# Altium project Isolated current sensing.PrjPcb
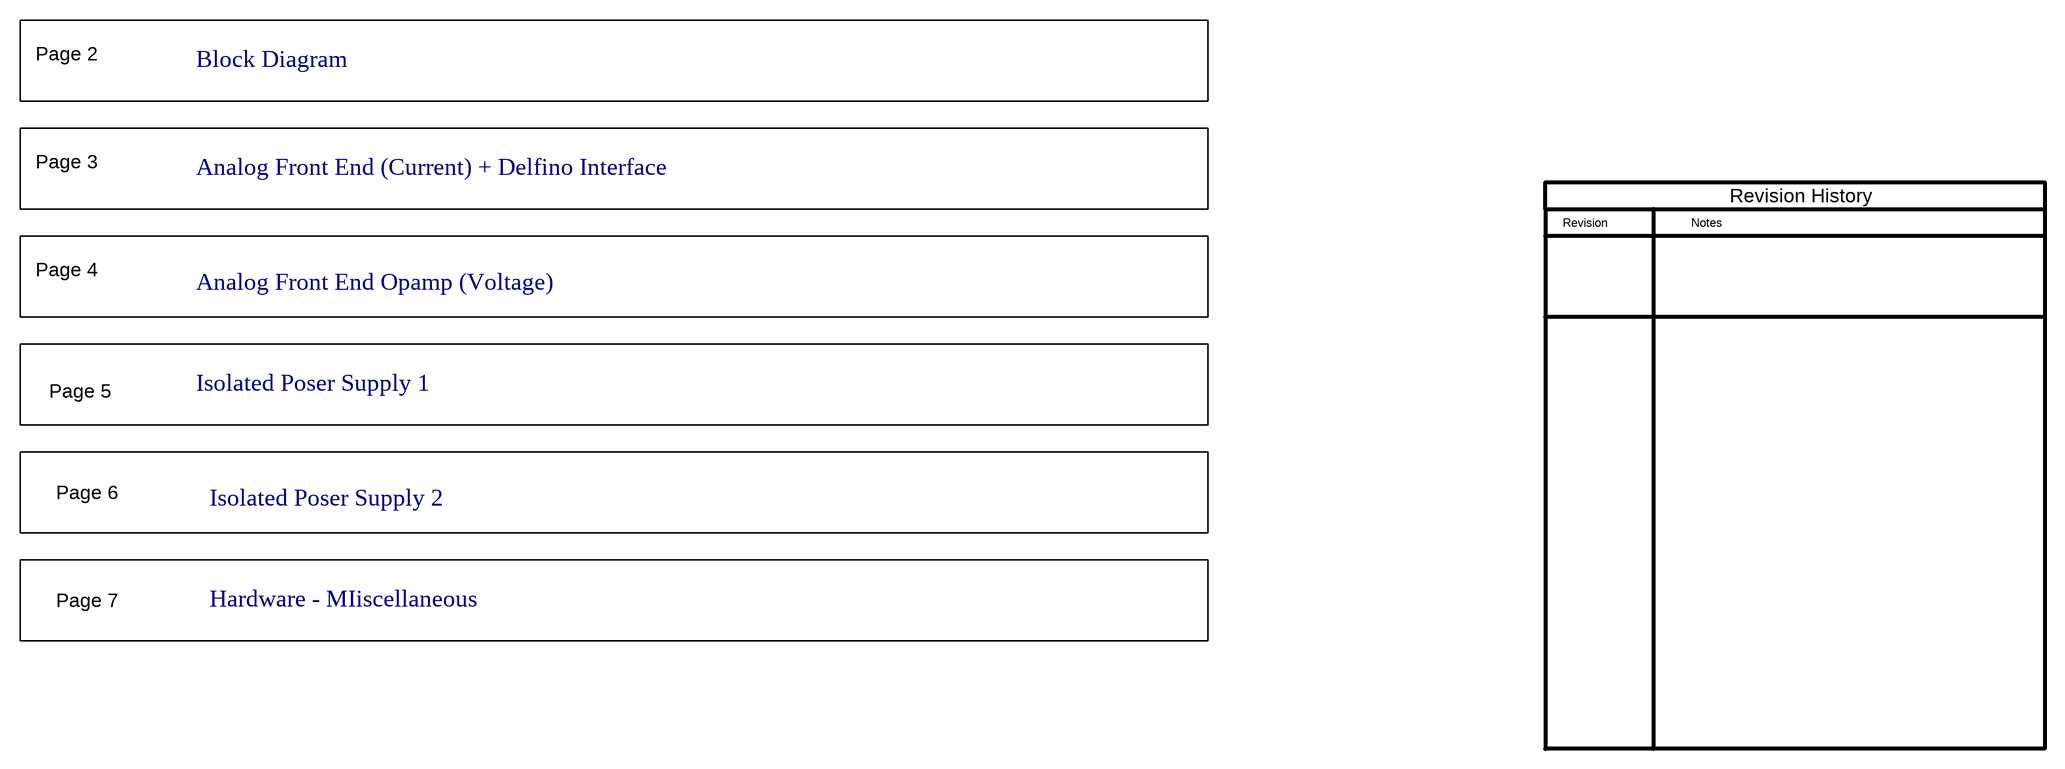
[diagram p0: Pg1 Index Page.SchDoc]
CopyrightYear: 2014; PCB_Layout: Vamsi T; PCB_Rev: E1; PRJ_Customer: Public Release; PRJ_Engineer: Prahlad Supeda; PRJ_Number: TIDA-00080; PRJ_Title: TIDA-00080 - ISE3010; SCH_Rev: E1; TechSupport: http://www.ti.com/support
7 sheets, 364 parts. Net scope: flat (ports and power ports of the same name join across sheets).
Board file: TIDAA-00080.PcbDoc
Sheets:
  Pg1 Index Page.SchDoc
  Pg2 Block Diagram.SchDoc
  Pg3-Current Sense.SchDoc
  Pg4-Voltage signal condtioning.SchDoc
  Pg5-Power supply 1.SchDoc
  Pg6-Power supply 2.SchDoc
  Pg7-Hardware.SchDoc

## Sheet Pg1 Index Page.SchDoc: Index Page
size 431 x 279 mm; Date: Not shown in title block; ApprovedBy: Not shown in title block; CheckedBy: Not shown in title block; Author: Not shown in title block; CompanyName: Not shown in title block; Engineer: Not shown in title block; Organization: Not shown in title block; Address1: Not shown in title block; Address2: Not shown in title block; Address3: Not shown in title block; Address4: Not shown in title block; DocumentNumber: 1; Revision: Use project parameter SCH_Rev; SheetNumber: 1; SheetTotal: 7; PageSetup: Record=PageOptions|CenterHorizontal=True|CenterVertical=True|PrintScale=1.00|XCorrection=1.00|YCorrection=1.00|PrintKind=0|BorderSize=5000000|LeftOffset=0|BottomOffset=0|Orientation=2|PaperLength=1000|PaperWidth=1000|Scale=100|PaperSource=15|PrintQuality=600|MediaType=1|DitherType=10|PaperKind=Letter|PrintScaleMode=1

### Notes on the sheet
- Page 2
- Block Diagram
- Page 3
- Analog Front End (Current) + Delfino Interface
- Revision
- Notes
- Revision History
- Page 4
- Analog Front End Opamp (Voltage)
- Page 5
- Isolated Poser Supply 1
- Page 6
- Isolated Poser Supply 2
- Page 7
- Hardware - MIiscellaneous

## Sheet Pg2 Block Diagram.SchDoc: Block Diagram
size 431 x 279 mm; Date: Not shown in title block; ApprovedBy: Not shown in title block; CheckedBy: Not shown in title block; Author: Not shown in title block; CompanyName: Not shown in title block; Engineer: Not shown in title block; Organization: Not shown in title block; Address1: Not shown in title block; Address2: Not shown in title block; Address3: Not shown in title block; Address4: Not shown in title block; DocumentNumber: 2; Revision: Use project parameter SCH_Rev; SheetNumber: 2; SheetTotal: 7; PageSetup: Record=PageOptions|CenterHorizontal=True|CenterVertical=True|PrintScale=1.00|XCorrection=1.00|YCorrection=1.00|PrintKind=0|BorderSize=5000000|LeftOffset=0|BottomOffset=0|Orientation=2|PaperLength=1000|PaperWidth=1000|Scale=100|PaperSource=15|PrintQuality=600|MediaType=1|DitherType=10|PaperKind=Letter|PrintScaleMode=1
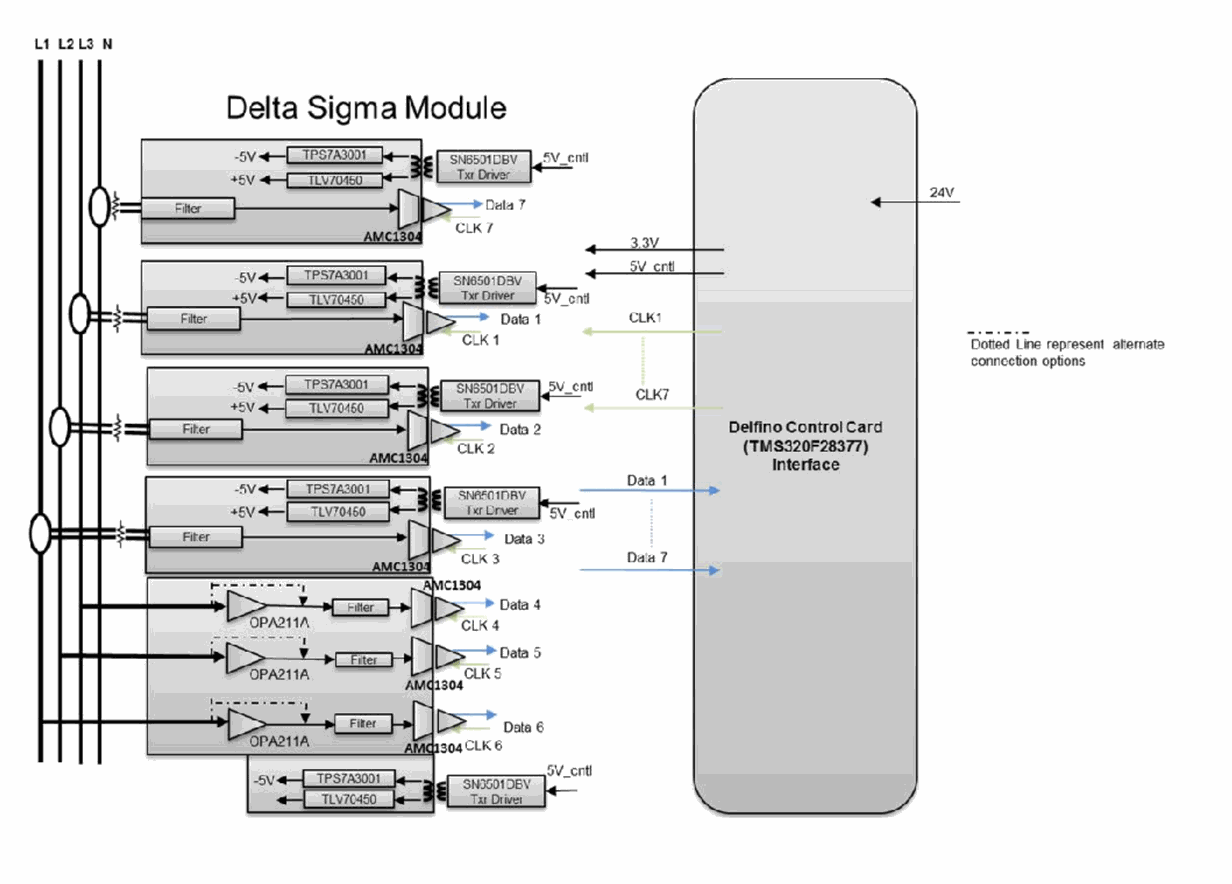
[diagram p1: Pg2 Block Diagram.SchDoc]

## Sheet Pg3-Current Sense.SchDoc: Analog Front End (Current) + Delfino Interface
size 431 x 279 mm; Date: Not shown in title block; ApprovedBy: Not shown in title block; CheckedBy: Not shown in title block; Author: Not shown in title block; CompanyName: Not shown in title block; Engineer: Not shown in title block; Organization: Not shown in title block; Address1: Not shown in title block; Address2: Not shown in title block; Address3: Not shown in title block; Address4: Not shown in title block; DocumentNumber: 3; Revision: Use project parameter SCH_Rev; SheetNumber: 3; SheetTotal: 7; PageSetup: Record=PageOptions|CenterHorizontal=True|CenterVertical=True|PrintScale=0.62|XCorrection=1.00|YCorrection=1.00|PrintKind=0|BorderSize=5000000|LeftOffset=0|BottomOffset=0|Orientation=2|PaperLength=1000|PaperWidth=1000|Scale=100|PaperSource=15|PrintQuality=600|MediaType=1|DitherType=10|PaperKind=Letter|PrintScaleMode=1
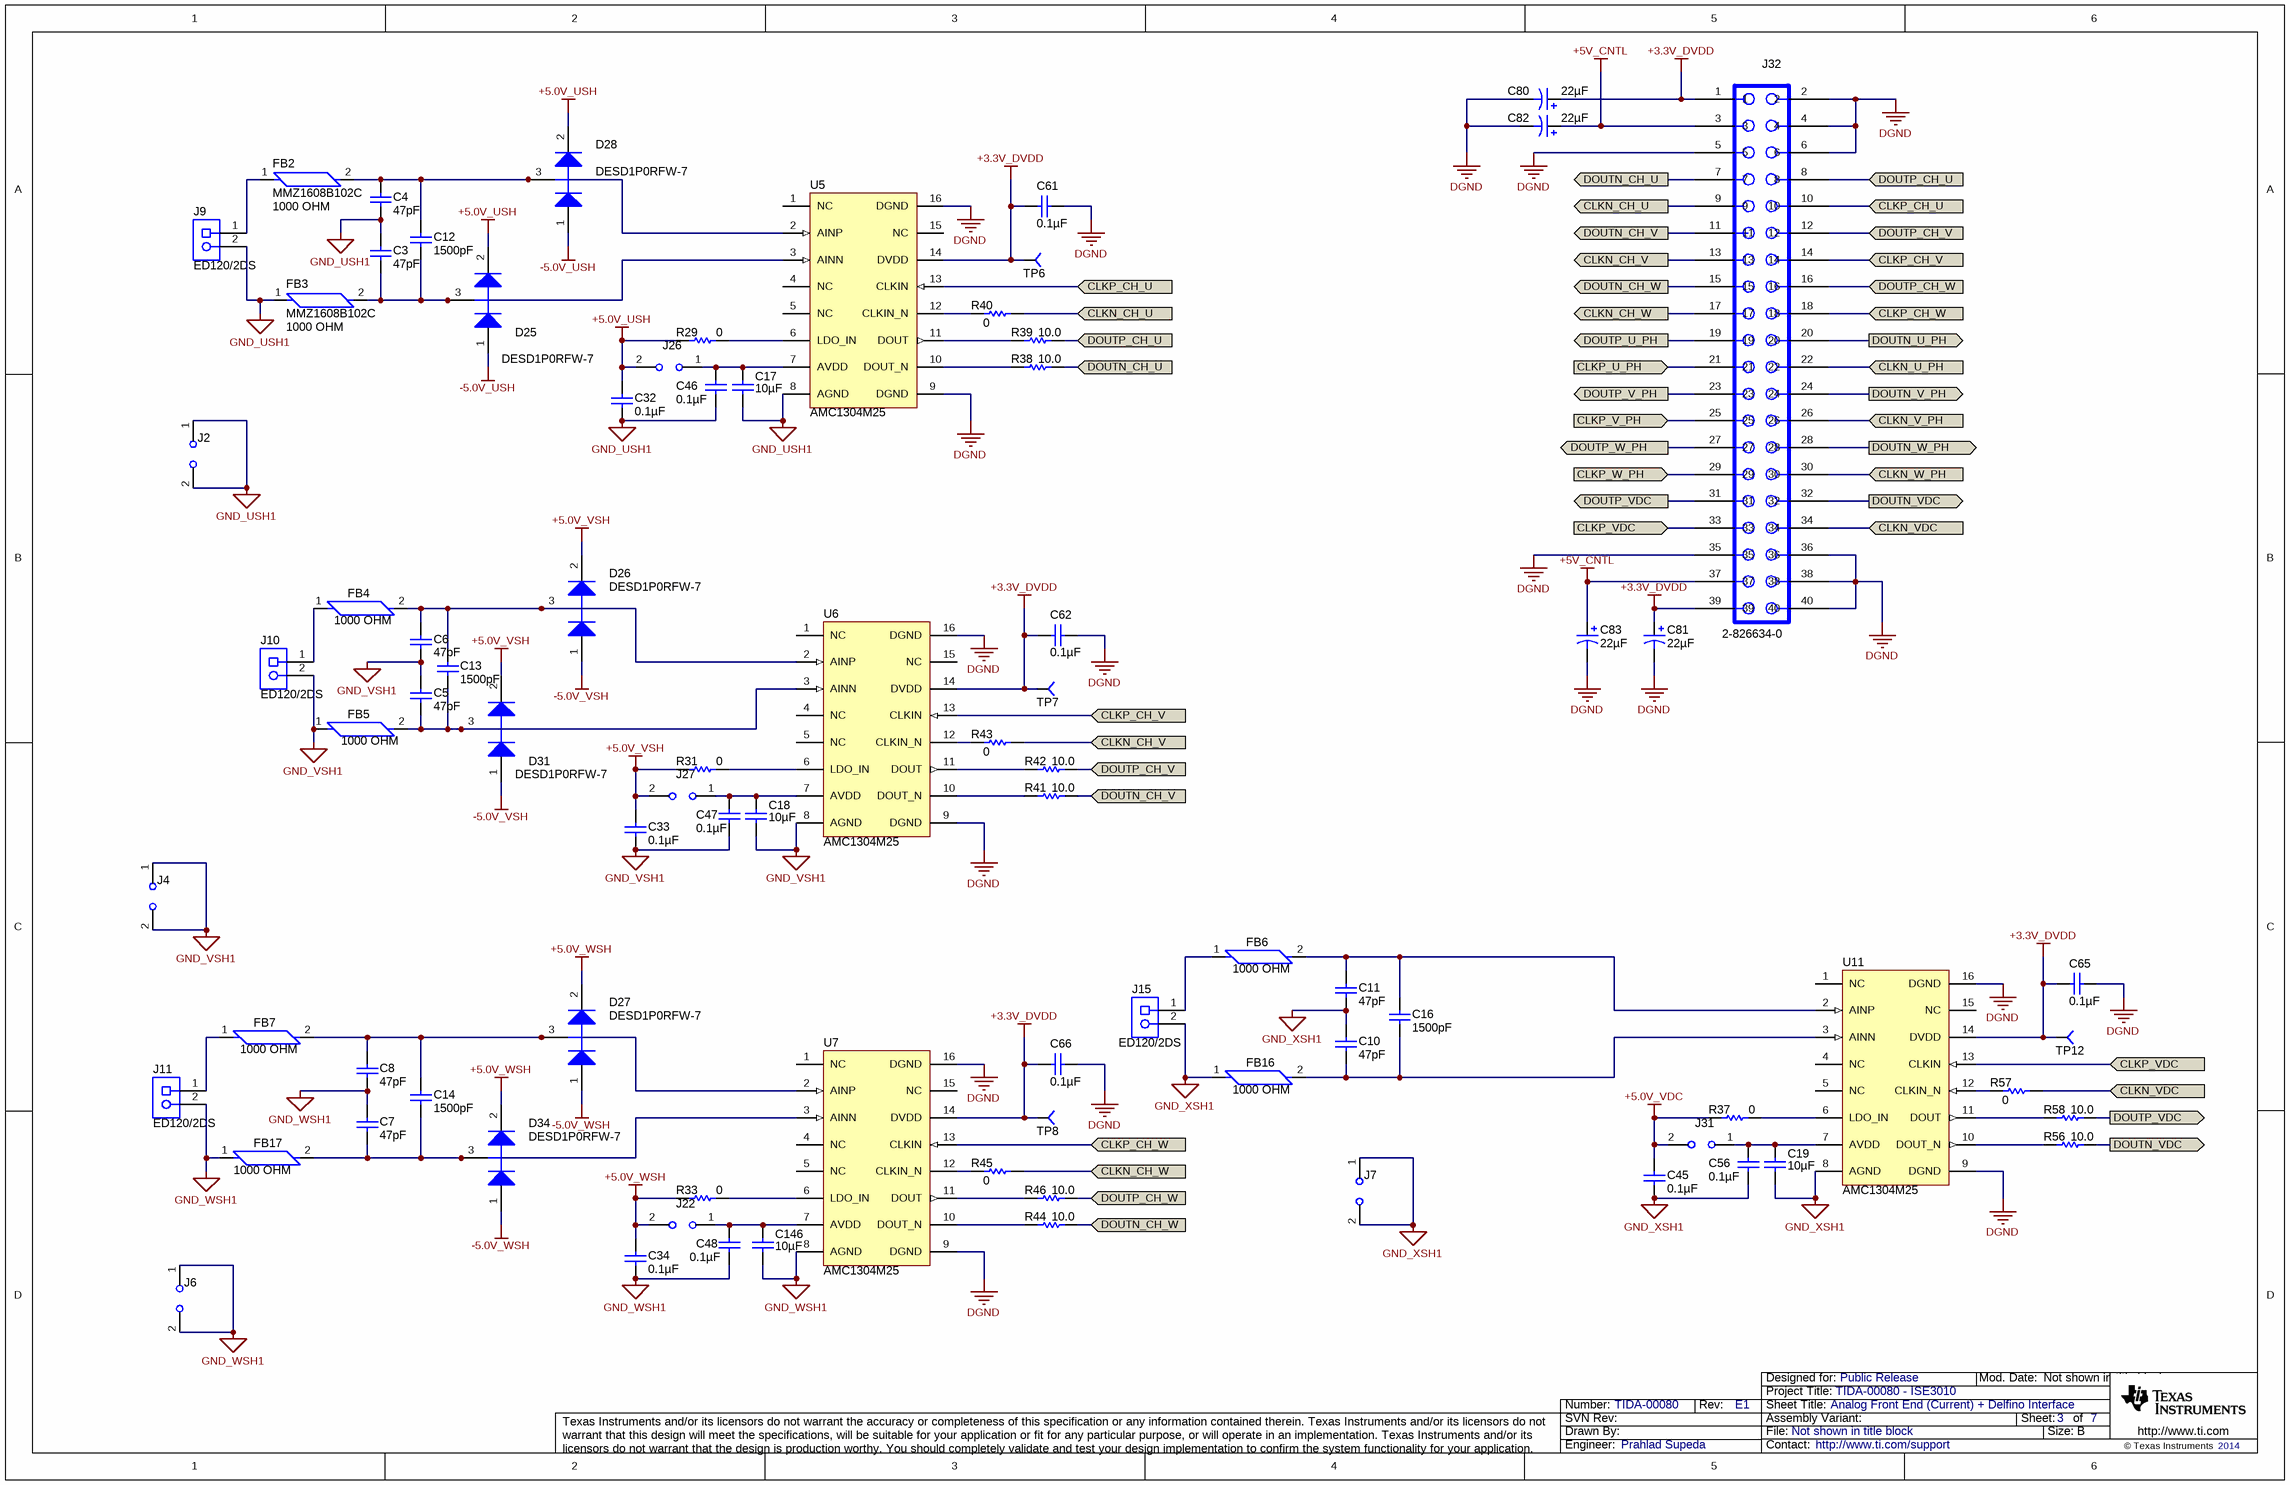
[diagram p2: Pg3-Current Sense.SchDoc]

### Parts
C3  ValueDisplayed: 47pF  [0805_HV]  (hidden comment: GRM21A5C2E470JW01D)
C4  ValueDisplayed: 47pF  [0805_HV]  (hidden comment: GRM21A5C2E470JW01D)
C5  ValueDisplayed: 47pF  [0805_HV]  (hidden comment: GRM21A5C2E470JW01D)
C6  ValueDisplayed: 47pF  [0805_HV]  (hidden comment: GRM21A5C2E470JW01D)
C7  ValueDisplayed: 47pF  [0805_HV]  (hidden comment: GRM21A5C2E470JW01D)
C8  ValueDisplayed: 47pF  [0805_HV]  (hidden comment: GRM21A5C2E470JW01D)
C10  ValueDisplayed: 47pF  [0805_HV]  (hidden comment: GRM21A5C2E470JW01D)
C11  ValueDisplayed: 47pF  [0805_HV]  (hidden comment: GRM21A5C2E470JW01D)
C12  ValueDisplayed: 1500pF  [0603]  (hidden comment: 06031C152KAT2A)
C13  ValueDisplayed: 1500pF  [0603]  (hidden comment: 06031C152KAT2A)
C14  ValueDisplayed: 1500pF  [0603]  (hidden comment: 06031C152KAT2A)
C16  ValueDisplayed: 1500pF  [0603]  (hidden comment: 06031C152KAT2A)
C17  ValueDisplayed: 10µF  [1210]
C18  ValueDisplayed: 10µF  [1210]
C19  ValueDisplayed: 10µF  [1210]
C32  ValueDisplayed: 0.1µF  [0603]
C33  ValueDisplayed: 0.1µF  [0603]
C34  ValueDisplayed: 0.1µF  [0603]
C45  ValueDisplayed: 0.1µF  [0603]
C46  ValueDisplayed: 0.1µF  [0603]
C47  ValueDisplayed: 0.1µF  [0603]
C48  ValueDisplayed: 0.1µF  [0603]
C56  ValueDisplayed: 0.1µF  [0603]
C61  ValueDisplayed: 0.1µF  [0603]
C62  ValueDisplayed: 0.1µF  [0603]
C65  ValueDisplayed: 0.1µF  [0603]
C66  ValueDisplayed: 0.1µF  [0603]
C80  ValueDisplayed: 22µF  [SM_RADIAL_5MM]  (hidden comment: UUD1E220MCL1GS)
C81  ValueDisplayed: 22µF  [SM_RADIAL_5MM]  (hidden comment: UUD1E220MCL1GS)
C82  ValueDisplayed: 22µF  [SM_RADIAL_5MM]  (hidden comment: UUD1E220MCL1GS)
C83  ValueDisplayed: 22µF  [SM_RADIAL_5MM]  (hidden comment: UUD1E220MCL1GS)
C146  ValueDisplayed: 10µF  [1210]
D25  value DESD1P0RFW-7  [SOT-323]
D26  DESD1P0RFW-7  [SOT-323]
D27  DESD1P0RFW-7  [SOT-323]
D28  value DESD1P0RFW-7  [SOT-323]
D31  DESD1P0RFW-7  [SOT-323]
D34  DESD1P0RFW-7  [SOT-323]
FB2  MMZ1608B102C  value 1000 OHM  [FB0603]
FB3  MMZ1608B102C  value 1000 OHM  [FB0603]
FB4  value 1000 OHM  [FB0603]  (hidden comment: MMZ1608B102C)
FB5  value 1000 OHM  [FB0603]  (hidden comment: MMZ1608B102C)
FB6  value 1000 OHM  [FB0603]  (hidden comment: MMZ1608B102C)
FB7  value 1000 OHM  [FB0603]  (hidden comment: MMZ1608B102C)
FB16  value 1000 OHM  [FB0603]  (hidden comment: MMZ1608B102C)
FB17  value 1000 OHM  [FB0603]  (hidden comment: MMZ1608B102C)
J2  (no value)  [HDR100_1X2]
J4  (no value)  [HDR100_1X2]
J6  (no value)  [HDR100_1X2]
J7  (no value)  [HDR100_1X2]
J9  ED120/2DS  [CONN_ED120-2DS]
J10  ED120/2DS  [CONN_ED120-2DS]
J11  ED120/2DS  [CONN_ED120-2DS]
J15  ED120/2DS  [CONN_ED120-2DS]
J22  (no value)  [HDR100_1X2]
J26  (no value)  [HDR100_1X2]
J27  (no value)  [HDR100_1X2]
J31  (no value)  [HDR100_1X2]
J32  2-826634-0  [CONN_61304021021]
R29  value 0  [0603]
R31  value 0  [0603]
R33  value 0  [0603]
R37  value 0  [0603]
R38  value 10.0  [0603]
R39  value 10.0  [0603]
R40  value 0  [0603]
R41  value 10.0  [0603]
R42  value 10.0  [0603]
R43  value 0  [0603]
R44  value 10.0  [0603]
R45  value 0  [0603]
R46  value 10.0  [0603]
R56  value 10.0  [0603]
R57  value 0  [0603]
R58  value 10.0  [0603]
TP6  (no value)  [TP-040_RND]
TP7  (no value)  [TP-040_RND]
TP8  (no value)  [TP-040_RND]
TP12  (no value)  [TP-040_RND]
U5  AMC1304M25  [DW0016A_N]
U6  AMC1304M25  [DW0016A_N]
U7  AMC1304M25  [DW0016A_N]
U11  AMC1304M25  [DW0016A_N]

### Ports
CLKN_CH_U, CLKN_CH_V, CLKN_CH_W, CLKN_U_PH (in), CLKN_V_PH (in), CLKN_VDC (in), CLKN_W_PH (in), CLKP_CH_U, CLKP_CH_V, CLKP_CH_W, CLKP_U_PH (in), CLKP_V_PH (in), CLKP_VDC (in), CLKP_W_PH (in), DOUTN_CH_U, DOUTN_CH_V, DOUTN_CH_W, DOUTN_U_PH (out), DOUTN_V_PH (out), DOUTN_VDC (out), DOUTN_W_PH (out), DOUTP_CH_U, DOUTP_CH_V, DOUTP_CH_W, DOUTP_U_PH (out), DOUTP_V_PH (out), DOUTP_VDC (out), DOUTP_W_PH (out)

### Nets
+3.3V_DVDD: C61.2 C62.2 C65.2 C66.2 C80.1(+) C81.1(+) J32.1 J32.39 TP6.1 TP7.1 TP8.1 TP12.1 U5.14(DVDD) U6.14(DVDD) U7.14(DVDD) U11.14(DVDD)
+5.0V_USH: C32.1 D25.2(K) D28.2(K) J26.2 R29.1
+5.0V_VDC: C45.1 J31.2 R37.1
+5.0V_VSH: C33.1 D26.2(K) D31.2(K) J27.2 R31.1
+5.0V_WSH: C34.1 D27.2(K) D34.2(K) J22.2 R33.1
+5V_CNTL: C82.1(+) C83.1(+) J32.3 J32.37
-5.0V_USH: D25.1(A) D28.1(A)
-5.0V_VSH: D26.1(A) D31.1(A)
-5.0V_WSH: D27.1(A) D34.1(A)
DGND: C61.1 C62.1 C65.1 C66.1 C80.2(-) C81.2(-) C82.2(-) C83.2(-) J32.2 J32.4 J32.5 J32.6 J32.35 J32.36 J32.38 J32.40 U5.9(DGND) U5.16(DGND) U6.9(DGND) U6.16(DGND) U7.9(DGND) U7.16(DGND) U11.9(DGND) U11.16(DGND)
GND_USH1: C3.1 C4.2 C17.1 C32.2 C46.2 FB3.1 J2.1 J2.2 J9.2 U5.8(AGND)
GND_VSH1: C5.1 C6.2 C18.1 C33.2 C47.2 FB5.1 J4.1 J4.2 J10.2 U6.8(AGND)
GND_WSH1: C7.1 C8.2 C34.2 C48.2 C146.1 FB17.1 J6.1 J6.2 J11.2 U7.8(AGND)
GND_XSH1: C10.1 C11.2 C19.1 C45.2 C56.2 FB16.1 J7.1 J7.2 J15.2 U11.8(AGND)
CLKN_CH_U: J32.9 R40.2 ; port CLKN_CH_U
CLKN_CH_V: J32.13 R43.2 ; port CLKN_CH_V
CLKN_CH_W: J32.17 R45.2 ; port CLKN_CH_W
CLKN_U_PH: J32.22 ; port CLKN_U_PH
CLKN_V_PH: J32.26 ; port CLKN_V_PH
CLKN_VDC: J32.34 R57.2 ; port CLKN_VDC
CLKN_W_PH: J32.30 ; port CLKN_W_PH
CLKP_CH_U: J32.10 U5.13(CLKIN) ; port CLKP_CH_U
CLKP_CH_V: J32.14 U6.13(CLKIN) ; port CLKP_CH_V
CLKP_CH_W: J32.18 U7.13(CLKIN) ; port CLKP_CH_W
CLKP_U_PH: J32.21 ; port CLKP_U_PH
CLKP_V_PH: J32.25 ; port CLKP_V_PH
CLKP_VDC: J32.33 U11.13(CLKIN) ; port CLKP_VDC
CLKP_W_PH: J32.29 ; port CLKP_W_PH
DOUTN_CH_U: J32.7 R38.2 ; port DOUTN_CH_U
DOUTN_CH_V: J32.11 R41.2 ; port DOUTN_CH_V
DOUTN_CH_W: J32.15 R44.2 ; port DOUTN_CH_W
DOUTN_U_PH: J32.20 ; port DOUTN_U_PH
DOUTN_V_PH: J32.24 ; port DOUTN_V_PH
DOUTN_VDC: J32.32 R56.2 ; port DOUTN_VDC
DOUTN_W_PH: J32.28 ; port DOUTN_W_PH
DOUTP_CH_U: J32.8 R39.2 ; port DOUTP_CH_U
DOUTP_CH_V: J32.12 R42.2 ; port DOUTP_CH_V
DOUTP_CH_W: J32.16 R46.2 ; port DOUTP_CH_W
DOUTP_U_PH: J32.19 ; port DOUTP_U_PH
DOUTP_V_PH: J32.23 ; port DOUTP_V_PH
DOUTP_VDC: J32.31 R58.2 ; port DOUTP_VDC
DOUTP_W_PH: J32.27 ; port DOUTP_W_PH
NetC3_2: C3.2 C12.2 D25.3(C) FB3.2 U5.3(AINN)
NetC4_1: C4.1 C12.1 D28.3(C) FB2.2 U5.2(AINP)
NetC5_2: C5.2 C13.2 D31.3(C) FB5.2 U6.3(AINN)
NetC6_1: C6.1 C13.1 D26.3(C) FB4.2 U6.2(AINP)
NetC7_2: C7.2 C14.2 D34.3(C) FB17.2 U7.3(AINN)
NetC8_1: C8.1 C14.1 D27.3(C) FB7.2 U7.2(AINP)
NetC10_2: C10.2 C16.2 FB16.2 U11.3(AINN)
NetC11_1: C11.1 C16.1 FB6.2 U11.2(AINP)
NetC17_2: C17.2 C46.1 J26.1 U5.7(AVDD)
NetC18_2: C18.2 C47.1 J27.1 U6.7(AVDD)
NetC19_2: C19.2 C56.1 J31.1 U11.7(AVDD)
NetC48_1: C48.1 C146.2 J22.1 U7.7(AVDD)
NetFB2_1: FB2.1 J9.1
NetFB4_1: FB4.1 J10.1
NetFB6_1: FB6.1 J15.1
NetFB7_1: FB7.1 J11.1
NetR29_2: R29.2 U5.6(LDO_IN)
NetR31_2: R31.2 U6.6(LDO_IN)
NetR33_2: R33.2 U7.6(LDO_IN)
NetR37_2: R37.2 U11.6(LDO_IN)
NetR38_1: R38.1 U5.10(DOUT_N)
NetR39_1: R39.1 U5.11(DOUT)
NetR40_1: R40.1 U5.12(CLKIN_N)
NetR41_1: R41.1 U6.10(DOUT_N)
NetR42_1: R42.1 U6.11(DOUT)
NetR43_1: R43.1 U6.12(CLKIN_N)
NetR44_1: R44.1 U7.10(DOUT_N)
NetR45_1: R45.1 U7.12(CLKIN_N)
NetR46_1: R46.1 U7.11(DOUT)
NetR56_1: R56.1 U11.10(DOUT_N)
NetR57_1: R57.1 U11.12(CLKIN_N)
NetR58_1: R58.1 U11.11(DOUT)

Not connected (* = marked no-connect by the designer): U5 1(NC) 4(NC) 5(NC) 15(NC); U6 1(NC) 4(NC) 5(NC) 15(NC); U7 1(NC) 4(NC) 5(NC) 15(NC); U11 1(NC) 4(NC) 5(NC) 15(NC)

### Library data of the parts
C3-C8 C10 C11 = GRM21A5C2E470JW01D: CAP, CERM, 47pF, 500V, +/-5%, C0G/NP0, 0805; Manufacturer: MuRata; Polarized: N; CompType: Capacitor; U/M: EA; Cap_F: 0.000000000047; Tolerance_%: 5; Value1: Unknown; VDC_V: 250; Value2: 250V; TaMin_C: -55; TaMax_C: 125; Cap_Case: 0805
C12-C14 C16 = 06031C152KAT2A: CAP, CERM, 1500pF, 100V, +/-10%, X7R, 0603; Manufacturer: AVX; Polarized: N; CompType: Capacitor; U/M: EA; Cap_F: 0.0000000015; Tolerance_%: 10; ESR_Ohm: 0.229; Value1: 0.229 ohm; VDC_V: 100; TaMin_C: -55; TaMax_C: 125
C17-C19 C146 = GMK325AB7106MM-T: CAP, CERM, 10uF, 35V, +/-20%, X7R, 1210; Manufacturer: Taiyo Yuden; Polarized: N; CompType: Capacitor; U/M: EA; Cap_F: 0.00001; Tolerance_%: 20; Value1: Unknown; VDC_V: 35; TaMin_C: -55; TaMax_C: 125
C32-C34 C45-C48 C56 = C0603C104K5RACTU: CAP, CERM, 0.1uF, 50V, +/-10%, X7R, 0603; Manufacturer: Kemet; Polarized: N; CompType: Capacitor; U/M: EA; Cap_F: 0.0000001; Tolerance_%: 10; Value1: Unknown; VDC_V: 50; TaMin_C: -55; TaMax_C: 125
C61 C62 C65 C66 = 06033C104JAT2A: CAP, CERM, 0.1uF, 25V, +/-5%, X7R, 0603; Manufacturer: AVX; Polarized: N; CompType: Capacitor; U/M: EA; Cap_F: 0.0000001; Tolerance_%: 5; ESR_Ohm: 0.05; Value1: 0.05 ohm; VDC_V: 25; TaMin_C: -55; TaMax_C: 125
C80-C83 = UUD1E220MCL1GS: CAP, AL, 22uF, 25V, +/-20%, 0.76 ohm, SMD; Manufacturer: Nichicon; Polarized: Y; CompType: Capacitor; U/M: EA; Cap_F: 0.000022; Tolerance_%: 20; VDC_V: 25; ESR_Ohm: 0.76; IRMS_A: 0.15; TaMin_C: -55; TaMax_C: 105; Cap_Case: 5x5.8
D25 D28 = BAV99WT1G: Diode, P-N, 70V, 0.2A, SOT-323; Manufacturer: Diodes Inc
D26 D27 D31 D34 = BAV99WT1G: Diode, P-N, 70V, 0.2A, SOT-323; Manufacturer: Diodes Inc; Value: DNP
FB2-FB7 FB16 FB17 = MMZ1608B102C: FERRITE CHIP 1000 OHM 300MA 0603; Manufacturer: TDK Corporation; CompType: Ferrite Bead
J2 J4 J6 J7 J22 J26 J27 J31 = JUMPER_2X100MIL: Header, Male 2-pin, 100mil spacing,; Manufacturer: FCI; PartNumber: 68001-402HLF; area: 20000; Value: 68001-402HLF
J9-J11 J15 = ED120/2DS: TERMINAL BLOCK 5.08MM VERT 2POS, TH; Manufacturer: On-Shore Technology; SymbolCreator: a0412235; U/M: EA
J32 = CONN_61304021021: Connector, Right Angle 2x20 pin, 100mil spacing; Manufacturer: TE Connectivity; area: 1.262.250
R29 R31 R33 R37 R40 R43 R45 R57 = CRCW06030000Z0EA: RES, 0 ohm, 5%, 0.1W, 0603; Manufacturer: Vishay-Dale; CompType: Resistor; Value_Code: 0000; Tolerance_%: 5; Power_W: 0.1; VDC_V: 75; TempCo: 200 ppm/C; EIA_Code: E24; U/M: EA
R38 R39 R41 R42 R44 R46 R56 R58 = CRCW060310R0FKEA: RES, 10.0 ohm, 1%, 0.1W, 0603; Manufacturer: Vishay-Dale; CompType: Resistor; Res_ohm: 10; Value_Code: 10R0; Tolerance_%: 1; Power_W: 0.1; VDC_V: 75; TempCo: 100 ppm/C; EIA_Code: E96; U/M: EA
TP6-TP8 TP12 = TP-040_RND: Test Point, O.040 Hole; Manufacturer: STD; Value: STD
U5-U7 U11 = AMC1304L25: 20 MHz, Isolated Delta-Sigma Modulator, LVDS interface:; Alternate Manufacturer: None; Manufacturer: Texas Instruments; SymbolCreator: x0120606; CompType: IC

## Sheet Pg4-Voltage signal condtioning.SchDoc: Analog Front End Opamp (Voltage)
size 431 x 279 mm; Date: Not shown in title block; ApprovedBy: Not shown in title block; CheckedBy: Not shown in title block; Author: Not shown in title block; CompanyName: Not shown in title block; Engineer: Not shown in title block; Organization: Not shown in title block; Address1: Not shown in title block; Address2: Not shown in title block; Address3: Not shown in title block; Address4: Not shown in title block; DocumentNumber: 4; Revision: Use project parameter SCH_Rev; SheetNumber: 4; SheetTotal: 7; PageSetup: Record=PageOptions|CenterHorizontal=True|CenterVertical=True|PrintScale=1.00|XCorrection=1.00|YCorrection=1.00|PrintKind=0|BorderSize=5000000|LeftOffset=0|BottomOffset=0|Orientation=2|PaperLength=1000|PaperWidth=1000|Scale=100|PaperSource=15|PrintQuality=600|MediaType=1|DitherType=10|PaperKind=Letter|PrintScaleMode=1
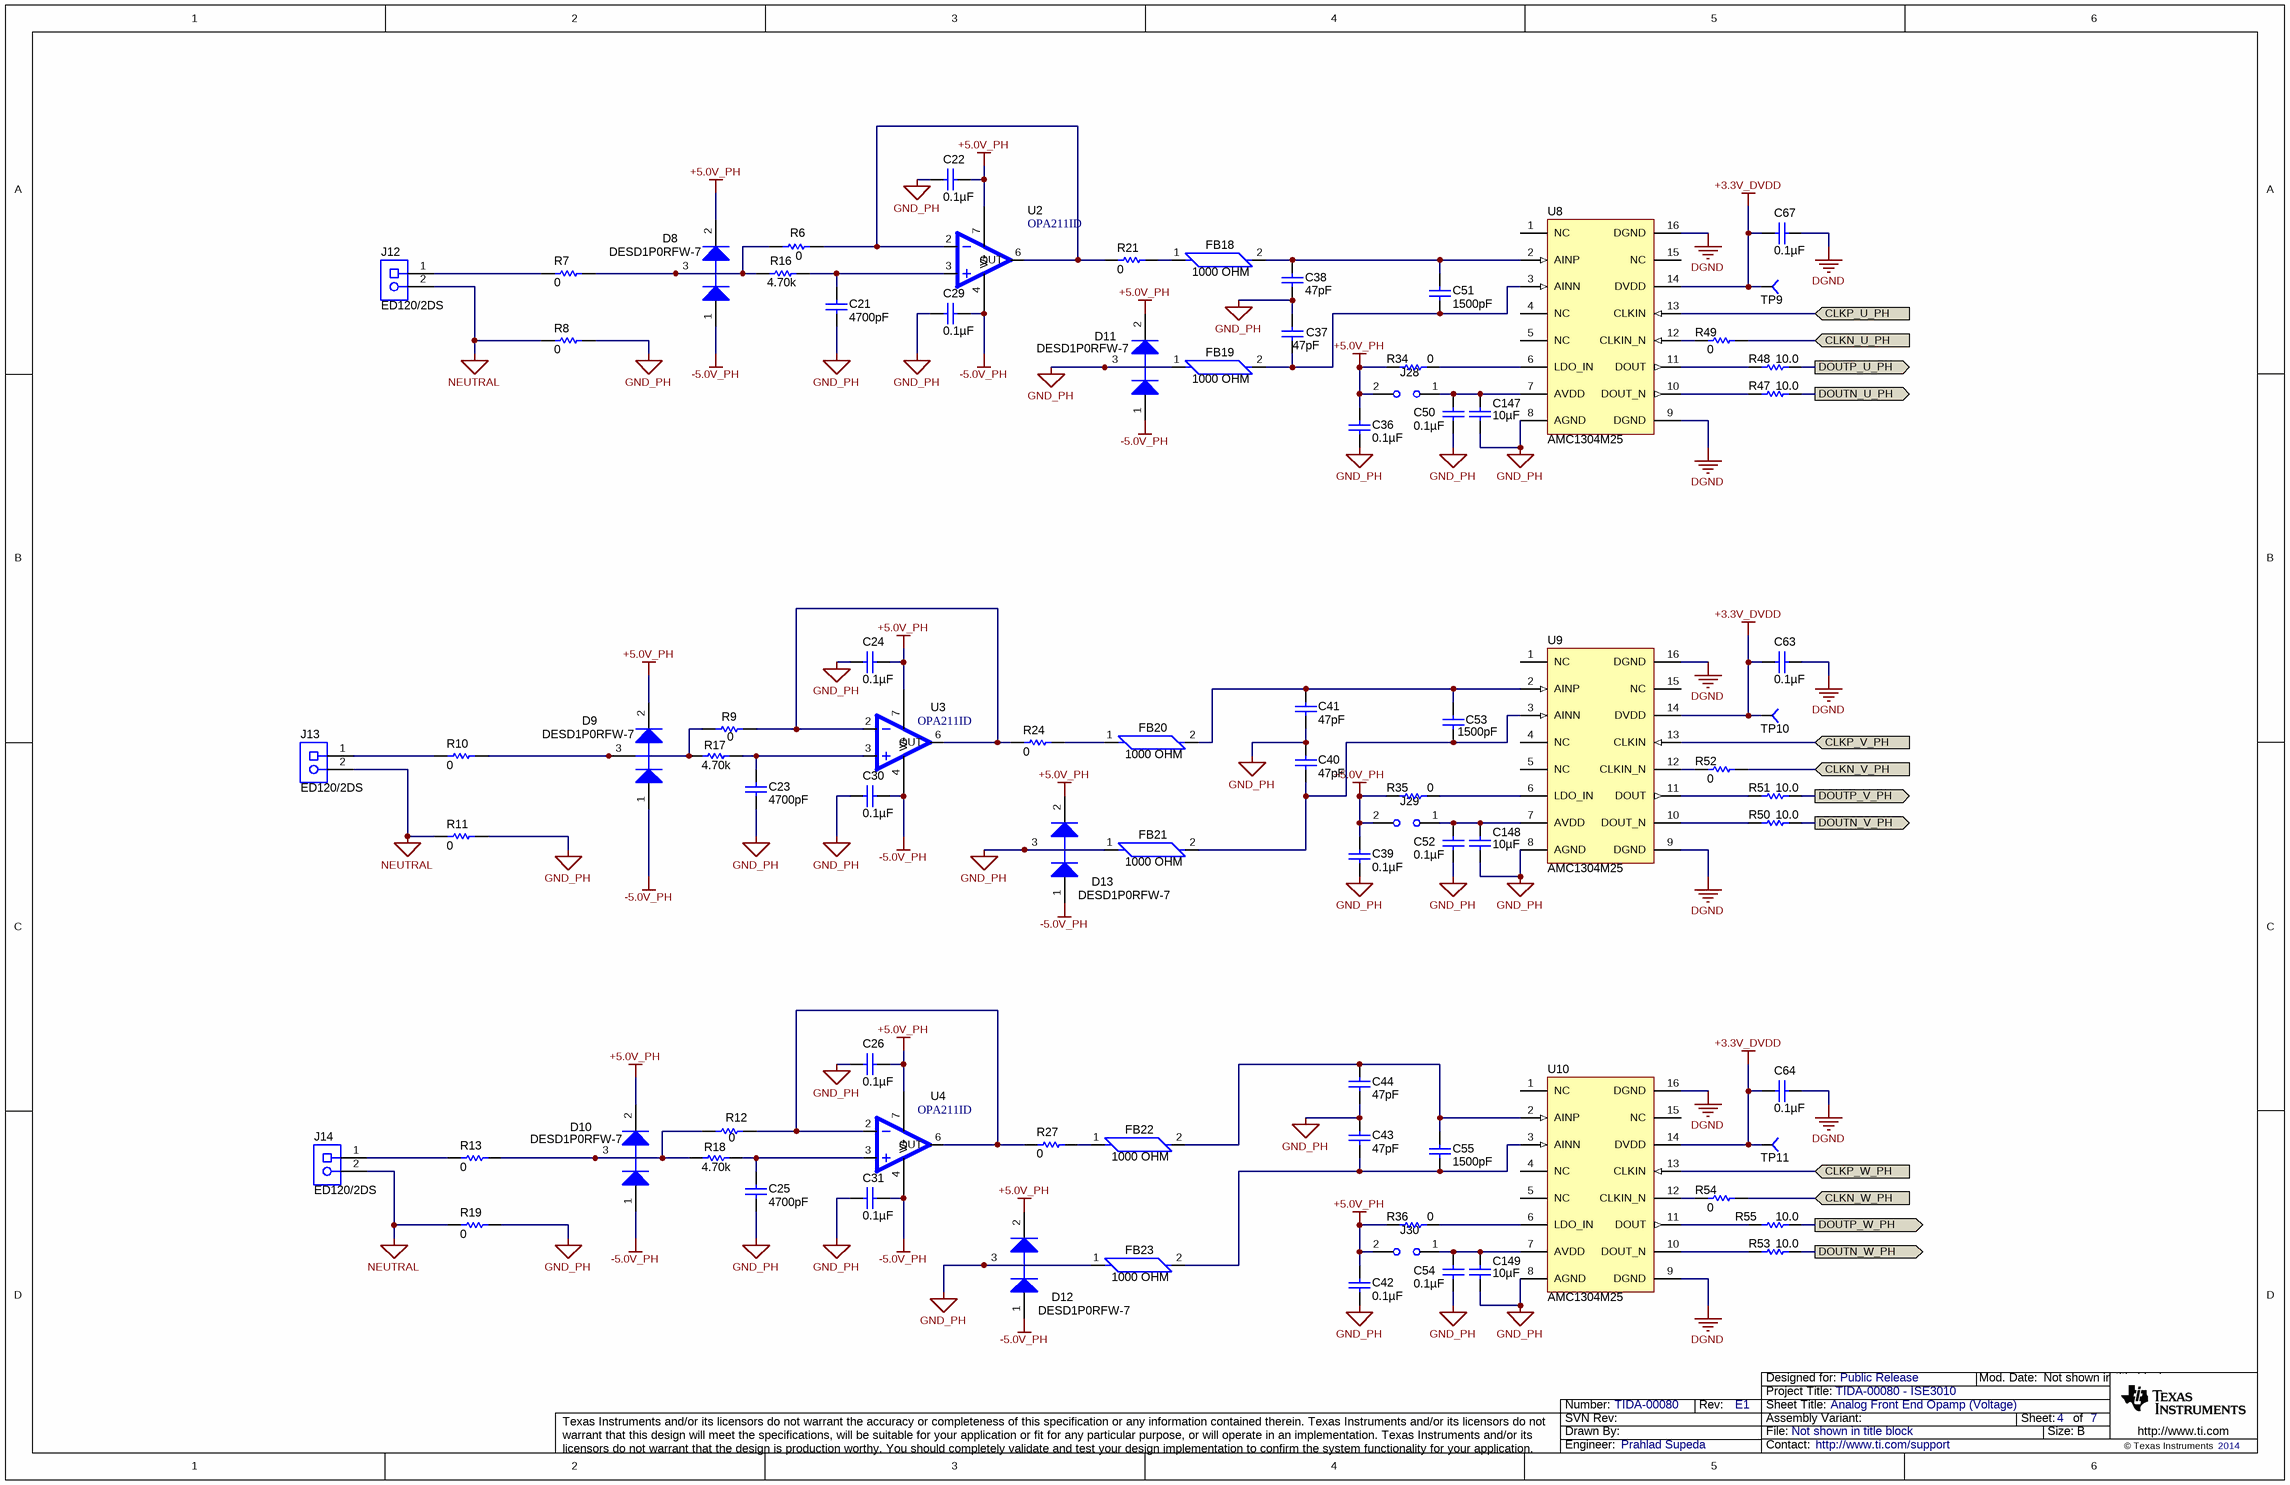
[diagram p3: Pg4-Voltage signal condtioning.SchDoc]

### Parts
C21  ValueDisplayed: 4700pF  [0603]
C22  ValueDisplayed: 0.1µF  [0603]
C23  ValueDisplayed: 4700pF  [0603]
C24  ValueDisplayed: 0.1µF  [0603]
C25  ValueDisplayed: 4700pF  [0603]
C26  ValueDisplayed: 0.1µF  [0603]
C29  ValueDisplayed: 0.1µF  [0603]
C30  ValueDisplayed: 0.1µF  [0603]
C31  ValueDisplayed: 0.1µF  [0603]
C36  ValueDisplayed: 0.1µF  [0603]
C37  ValueDisplayed: 47pF  [0805_HV]  (hidden comment: GRM21A5C2E470JW01D)
C38  ValueDisplayed: 47pF  [0805_HV]  (hidden comment: GRM21A5C2E470JW01D)
C39  ValueDisplayed: 0.1µF  [0603]
C40  ValueDisplayed: 47pF  [0805_HV]  (hidden comment: GRM21A5C2E470JW01D)
C41  ValueDisplayed: 47pF  [0805_HV]  (hidden comment: GRM21A5C2E470JW01D)
C42  ValueDisplayed: 0.1µF  [0603]
C43  ValueDisplayed: 47pF  [0805_HV]  (hidden comment: GRM21A5C2E470JW01D)
C44  ValueDisplayed: 47pF  [0805_HV]  (hidden comment: GRM21A5C2E470JW01D)
C50  ValueDisplayed: 0.1µF  [0603]
C51  ValueDisplayed: 1500pF  [0603]  (hidden comment: 06031C152KAT2A)
C52  ValueDisplayed: 0.1µF  [0603]
C53  ValueDisplayed: 1500pF  [0603]  (hidden comment: 06031C152KAT2A)
C54  ValueDisplayed: 0.1µF  [0603]
C55  ValueDisplayed: 1500pF  [0603]  (hidden comment: 06031C152KAT2A)
C63  ValueDisplayed: 0.1µF  [0603]
C64  ValueDisplayed: 0.1µF  [0603]
C67  ValueDisplayed: 0.1µF  [0603]
C147  ValueDisplayed: 10µF  [1210]
C148  ValueDisplayed: 10µF  [1210]
C149  ValueDisplayed: 10µF  [1210]
D8  DESD1P0RFW-7  [SOT-323]
D9  DESD1P0RFW-7  [SOT-323]
D10  DESD1P0RFW-7  [SOT-323]
D11  value DESD1P0RFW-7  [SOT-323]
D12  value DESD1P0RFW-7  [SOT-323]
D13  value DESD1P0RFW-7  [SOT-323]
FB18  value 1000 OHM  [FB0603]  (hidden comment: MMZ1608B102C)
FB19  value 1000 OHM  [FB0603]  (hidden comment: MMZ1608B102C)
FB20  value 1000 OHM  [FB0603]  (hidden comment: MMZ1608B102C)
FB21  value 1000 OHM  [FB0603]  (hidden comment: MMZ1608B102C)
FB22  value 1000 OHM  [FB0603]  (hidden comment: MMZ1608B102C)
FB23  value 1000 OHM  [FB0603]  (hidden comment: MMZ1608B102C)
J12  ED120/2DS  [CONN_ED120-2DS]
J13  ED120/2DS  [CONN_ED120-2DS]
J14  ED120/2DS  [CONN_ED120-2DS]
J28  (no value)  [HDR100_1X2]
J29  (no value)  [HDR100_1X2]
J30  (no value)  [HDR100_1X2]
R6  value 0  [0603]  (hidden comment: CRCW06030000Z0EA)
R7  value 0  [0805_HV]  (hidden comment: CRCW08050000Z0EA)
R8  value 0  [0805_HV]  (hidden comment: CRCW08050000Z0EA)
R9  value 0  [0603]  (hidden comment: CRCW06030000Z0EA)
R10  value 0  [0805_HV]  (hidden comment: CRCW08050000Z0EA)
R11  value 0  [0805_HV]  (hidden comment: CRCW08050000Z0EA)
R12  value 0  [0603]  (hidden comment: CRCW06030000Z0EA)
R13  value 0  [0805_HV]  (hidden comment: CRCW08050000Z0EA)
R16  value 4.70k  [0603]
R17  value 4.70k  [0603]
R18  value 4.70k  [0603]
R19  value 0  [0805_HV]  (hidden comment: CRCW08050000Z0EA)
R21  value 0  [0603]
R24  value 0  [0603]
R27  value 0  [0603]
R34  value 0  [0603]
R35  value 0  [0603]
R36  value 0  [0603]
R47  value 10.0  [0603]
R48  value 10.0  [0603]
R49  value 0  [0603]
R50  value 10.0  [0603]
R51  value 10.0  [0603]
R52  value 0  [0603]
R53  value 10.0  [0603]
R54  value 0  [0603]
R55  value 10.0  [0603]
TP9  (no value)  [TP-040_RND]
TP10  (no value)  [TP-040_RND]
TP11  (no value)  [TP-040_RND]
U2  OPA211ID  [SO8]
U3  OPA211ID  [SO8]
U4  OPA211ID  [SO8]
U8  AMC1304M25  [DW0016A_N]
U9  AMC1304M25  [DW0016A_N]
U10  AMC1304M25  [DW0016A_N]

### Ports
CLKN_U_PH (in), CLKN_V_PH (in), CLKN_W_PH (in), CLKP_U_PH (in), CLKP_V_PH (in), CLKP_W_PH (in), DOUTN_U_PH (out), DOUTN_V_PH (out), DOUTN_W_PH (out), DOUTP_U_PH (out), DOUTP_V_PH (out), DOUTP_W_PH (out)

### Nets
+3.3V_DVDD: C63.2 C64.2 C67.2 TP9.1 TP10.1 TP11.1 U8.14(DVDD) U9.14(DVDD) U10.14(DVDD)
+5.0V_PH: C22.2 C24.2 C26.2 C36.1 C39.1 C42.1 D8.2(K) D9.2(K) D10.2(K) D11.2(K) D12.2(K) D13.2(K) J28.2 J29.2 J30.2 R34.1 R35.1 R36.1 U2.7(V+) U3.7(V+) U4.7(V+)
-5.0V_PH: C29.2 C30.2 C31.2 D8.1(A) D9.1(A) D10.1(A) D11.1(A) D12.1(A) D13.1(A) U2.4(V-) U3.4(V-) U4.4(V-)
DGND: C63.1 C64.1 C67.1 U8.9(DGND) U8.16(DGND) U9.9(DGND) U9.16(DGND) U10.9(DGND) U10.16(DGND)
GND_PH: C21.2 C22.1 C23.2 C24.1 C25.2 C26.1 C29.1 C30.1 C31.1 C36.2 C37.1 C38.1 C39.2 C40.1 C41.1 C42.2 C43.1 C44.1 C50.2 C52.2 C54.2 C147.1 C148.1 C149.1 D11.3(C) D12.3(C) D13.3(C) FB19.1 FB21.1 FB23.1 R8.2 R11.2 R19.2 U8.8(AGND) U9.8(AGND) U10.8(AGND)
NEUTRAL: J12.2 J13.2 J14.2 R8.1 R11.1 R19.1
CLKN_U_PH: R49.2 ; port CLKN_U_PH
CLKN_V_PH: R52.2 ; port CLKN_V_PH
CLKN_W_PH: R54.2 ; port CLKN_W_PH
CLKP_U_PH: U8.13(CLKIN) ; port CLKP_U_PH
CLKP_V_PH: U9.13(CLKIN) ; port CLKP_V_PH
CLKP_W_PH: U10.13(CLKIN) ; port CLKP_W_PH
DOUTN_U_PH: R47.2 ; port DOUTN_U_PH
DOUTN_V_PH: R50.2 ; port DOUTN_V_PH
DOUTN_W_PH: R53.2 ; port DOUTN_W_PH
DOUTP_U_PH: R48.2 ; port DOUTP_U_PH
DOUTP_V_PH: R51.2 ; port DOUTP_V_PH
DOUTP_W_PH: R55.2 ; port DOUTP_W_PH
NetC21_1: C21.1 R16.2 U2.3
NetC23_1: C23.1 R17.2 U3.3
NetC25_1: C25.1 R18.2 U4.3
NetC37_2: C37.2 C51.2 FB19.2 U8.3(AINN)
NetC38_2: C38.2 C51.1 FB18.2 U8.2(AINP)
NetC40_2: C40.2 C53.2 FB21.2 U9.3(AINN)
NetC41_2: C41.2 C53.1 FB20.2 U9.2(AINP)
NetC43_2: C43.2 C55.2 FB23.2 U10.3(AINN)
NetC44_2: C44.2 C55.1 FB22.2 U10.2(AINP)
NetC50_1: C50.1 C147.2 J28.1 U8.7(AVDD)
NetC52_1: C52.1 C148.2 J29.1 U9.7(AVDD)
NetC54_1: C54.1 C149.2 J30.1 U10.7(AVDD)
NetD8_3: D8.3(C) R6.1 R7.2 R16.1
NetD9_3: D9.3(C) R9.1 R10.2 R17.1
NetD10_3: D10.3(C) R12.1 R13.2 R18.1
NetFB18_1: FB18.1 R21.2
NetFB20_1: FB20.1 R24.2
NetFB22_1: FB22.1 R27.2
NetJ12_1: J12.1 R7.1
NetJ13_1: J13.1 R10.1
NetJ14_1: J14.1 R13.1
NetR6_2: R6.2 R21.1 U2.2 U2.6(OUT)
NetR9_2: R9.2 R24.1 U3.2 U3.6(OUT)
NetR12_2: R12.2 R27.1 U4.2 U4.6(OUT)
NetR34_2: R34.2 U8.6(LDO_IN)
NetR35_2: R35.2 U9.6(LDO_IN)
NetR36_2: R36.2 U10.6(LDO_IN)
NetR47_1: R47.1 U8.10(DOUT_N)
NetR48_1: R48.1 U8.11(DOUT)
NetR49_1: R49.1 U8.12(CLKIN_N)
NetR50_1: R50.1 U9.10(DOUT_N)
NetR51_1: R51.1 U9.11(DOUT)
NetR52_1: R52.1 U9.12(CLKIN_N)
NetR53_1: R53.1 U10.10(DOUT_N)
NetR54_1: R54.1 U10.12(CLKIN_N)
NetR55_1: R55.1 U10.11(DOUT)

Not connected (* = marked no-connect by the designer): U8 1(NC) 4(NC) 5(NC) 15(NC); U9 1(NC) 4(NC) 5(NC) 15(NC); U10 1(NC) 4(NC) 5(NC) 15(NC)

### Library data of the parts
C21 C23 C25 = 06031C472KAT2A: CAP, CERM, 4700pF, 100V, +/-10%, X7R, 0603; Manufacturer: AVX; Polarized: N; CompType: Capacitor; U/M: EA; Cap_F: 0.0000000047; Tolerance_%: 10; ESR_Ohm: 0.136; Value1: 0.136 ohm; VDC_V: 100; TaMin_C: -55; TaMax_C: 125
C22 C24 C26 C29-C31 C36 C39 C42 C50 C52 C54 = C0603C104K5RACTU: as C32 on sheet Pg3-Current Sense
C37 C38 C40 C41 C43 C44 = GRM21A5C2E470JW01D: as C3 on sheet Pg3-Current Sense
C51 C53 C55 = 06031C152KAT2A: as C12 on sheet Pg3-Current Sense
C63 C64 C67 = 06033C104JAT2A: as C61 on sheet Pg3-Current Sense
C147-C149 = GMK325AB7106MM-T: as C17 on sheet Pg3-Current Sense
D8-D10 = BAV99WT1G: as D26 on sheet Pg3-Current Sense
D11-D13 = BAV99WT1G: as D25 on sheet Pg3-Current Sense
FB18-FB23 = MMZ1608B102C: as FB2 on sheet Pg3-Current Sense
J12-J14 = ED120/2DS: as J9 on sheet Pg3-Current Sense
J28-J30 = JUMPER_2X100MIL: as J2 on sheet Pg3-Current Sense
R6 R9 R12 R21 R24 R27 R34-R36 R49 R52 R54 = CRCW06030000Z0EA: as R29 on sheet Pg3-Current Sense
R7 R8 R10 R11 R13 R19 = CRCW08050000Z0EA: RES, 0 ohm, 5%, 0.125W, 0805; Manufacturer: Vishay-Dale; CompType: Resistor; Value_Code: 0000; Tolerance_%: 5; Power_W: 0.125; VDC_V: 150; TempCo: 200 ppm/C; EIA_Code: E24; U/M: EA
R16-R18 = RC0603FR-074K7L: RES, 4.70k ohm, 1%, 0.1W, 0603; Manufacturer: Yageo America; CompType: Resistor; Res_ohm: 4700; Value_Code: 4k70; Tolerance_%: 1; Power_W: 0.1; VDC_V: 150; TempCo: 200 ppm/C; U/M: EA
R47 R48 R50 R51 R53 R55 = CRCW060310R0FKEA: as R38 on sheet Pg3-Current Sense
TP9-TP11 = TP-040_RND: as TP6 on sheet Pg3-Current Sense
U2-U4 = OPA211AID: IC, 1.1nV/vHz Noise, Low Power, Precision OpAmp; Manufacturer: Texas Instruments; Alternate Manufacturer: None; Area: 75900
U8-U10 = AMC1304L25: as U5 on sheet Pg3-Current Sense

## Sheet Pg5-Power supply 1.SchDoc: Isolated Poser Supply 1
size 431 x 279 mm; Date: Not shown in title block; ApprovedBy: Not shown in title block; CheckedBy: Not shown in title block; Author: Not shown in title block; CompanyName: Not shown in title block; Engineer: Not shown in title block; Organization: Not shown in title block; Address1: Not shown in title block; Address2: Not shown in title block; Address3: Not shown in title block; Address4: Not shown in title block; DocumentNumber: 5; Revision: Use project parameter SCH_Rev; SheetNumber: 5; SheetTotal: 7; PageSetup: Record=PageOptions|CenterHorizontal=True|CenterVertical=True|PrintScale=0.62|XCorrection=1.00|YCorrection=1.00|PrintKind=0|BorderSize=5000000|LeftOffset=0|BottomOffset=0|Orientation=2|PaperLength=1000|PaperWidth=1000|Scale=100|PaperSource=15|PrintQuality=600|MediaType=1|DitherType=10|PaperKind=Letter|PrintScaleMode=1
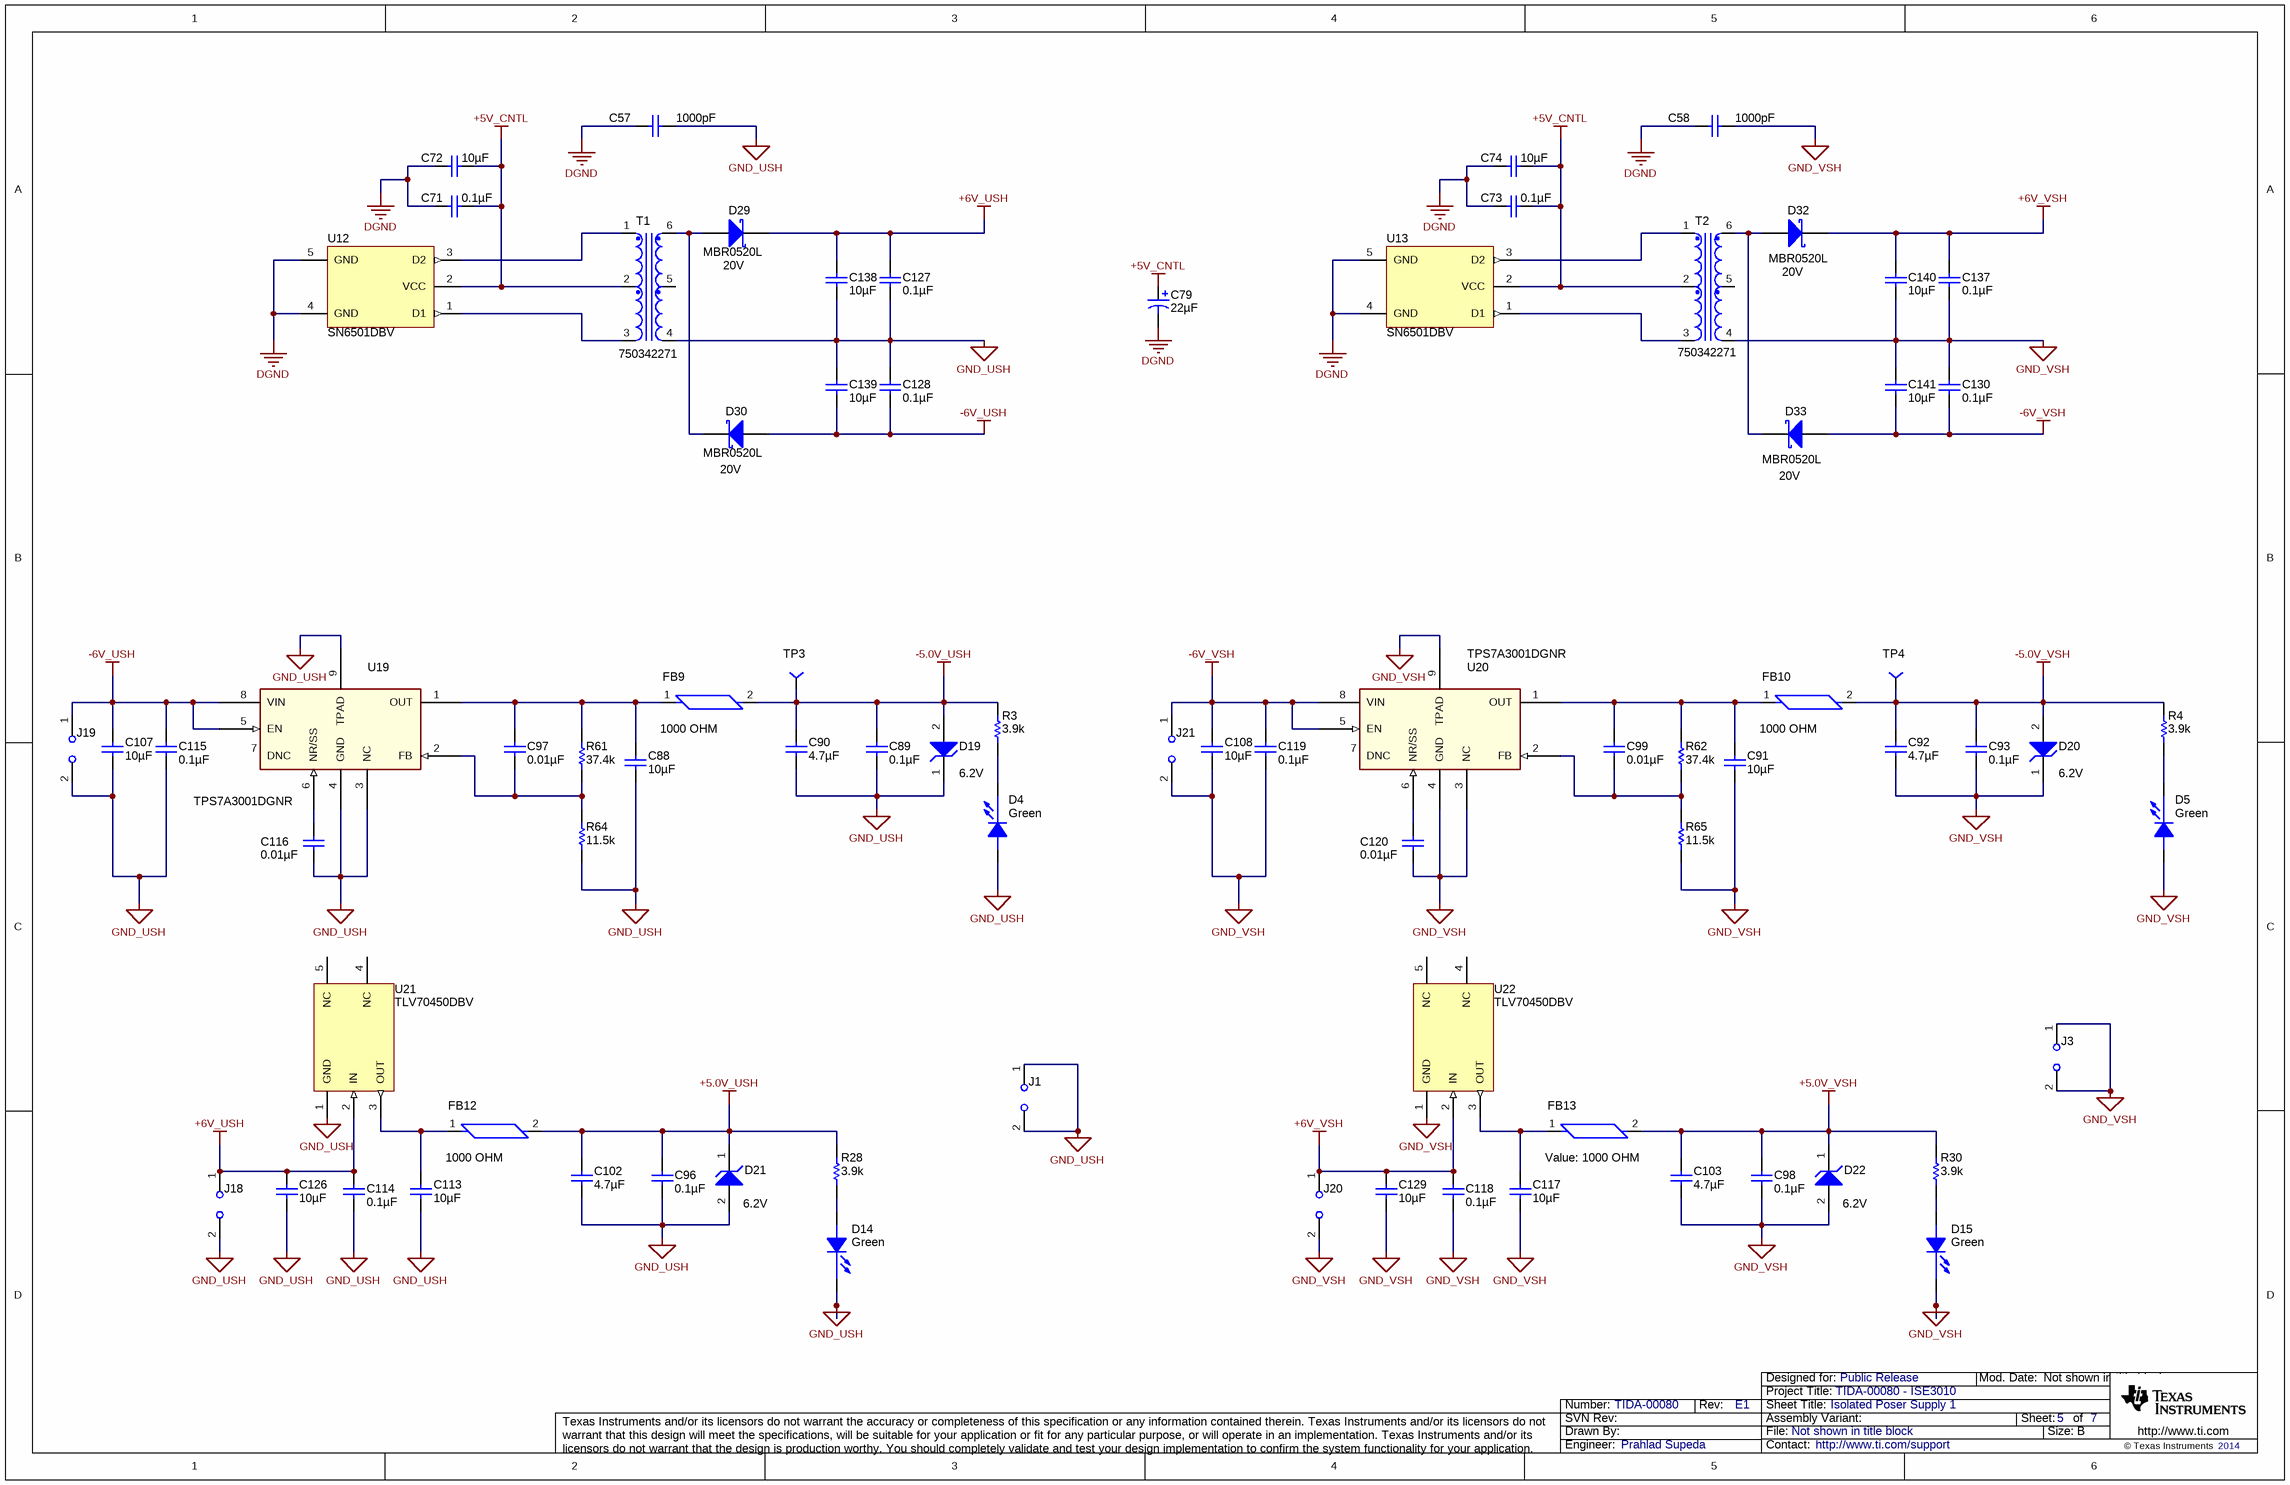
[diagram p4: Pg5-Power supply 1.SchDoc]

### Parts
C57  value 1000pF  [CAP_200mil]
C58  value 1000pF  [CAP_200mil]
C71  ValueDisplayed: 0.1µF  [0603]
C72  ValueDisplayed: 10µF  [1210]
C73  ValueDisplayed: 0.1µF  [0603]
C74  ValueDisplayed: 10µF  [1210]
C79  ValueDisplayed: 22µF  [SM_RADIAL_5MM]  (hidden comment: UUD1E220MCL1GS)
C88  ValueDisplayed: 10µF  [1210]
C89  ValueDisplayed: 0.1µF  [0603]
C90  ValueDisplayed: 4.7µF  [0805_HV]
C91  ValueDisplayed: 10µF  [1210]
C92  ValueDisplayed: 4.7µF  [0805_HV]
C93  ValueDisplayed: 0.1µF  [0603]
C96  ValueDisplayed: 0.1µF  [0603]
C97  ValueDisplayed: 0.01µF  [0603]
C98  ValueDisplayed: 0.1µF  [0603]
C99  ValueDisplayed: 0.01µF  [0603]
C102  ValueDisplayed: 4.7µF  [0805_HV]
C103  ValueDisplayed: 4.7µF  [0805_HV]
C107  ValueDisplayed: 10µF  [1210]
C108  ValueDisplayed: 10µF  [1210]
C113  ValueDisplayed: 10µF  [1210]
C114  ValueDisplayed: 0.1µF  [0603]
C115  ValueDisplayed: 0.1µF  [0603]
C116  ValueDisplayed: 0.01µF  [0603]
C117  ValueDisplayed: 10µF  [1210]
C118  ValueDisplayed: 0.1µF  [0603]
C119  ValueDisplayed: 0.1µF  [0603]
C120  ValueDisplayed: 0.01µF  [0603]
C126  ValueDisplayed: 10µF  [1210]
C127  ValueDisplayed: 0.1µF  [0603]
C128  ValueDisplayed: 0.1µF  [0603]
C129  ValueDisplayed: 10µF  [1210]
C130  ValueDisplayed: 0.1µF  [0603]
C137  ValueDisplayed: 0.1µF  [0603]
C138  ValueDisplayed: 10µF  [1210]
C139  ValueDisplayed: 10µF  [1210]
C140  ValueDisplayed: 10µF  [1210]
C141  ValueDisplayed: 10µF  [1210]
D4  value Green  [LED0603AA]
D5  value Green  [LED0603AA]
D14  value Green  [LED0603AA]
D15  value Green  [LED0603AA]
D19  value 6.2V  [powerDI123]
D20  value 6.2V  [powerDI123]
D21  value 6.2V  [powerDI123]
D22  value 6.2V  [powerDI123]
D29  MBR0520L  value 20V  [SOD-123]
D30  MBR0520L  value 20V  [SOD-123]
D32  MBR0520L  value 20V  [SOD-123]
D33  MBR0520L  value 20V  [SOD-123]
FB9  value 1000 OHM  [FB0603]
FB10  value 1000 OHM  [FB0603]
FB12  value 1000 OHM  [FB0603]
FB13  value 1000 OHM  [FB0603]
J1  (no value)  [HDR100_1X2]
J3  (no value)  [HDR100_1X2]
J18  (no value)  [HDR100_1X2]
J19  (no value)  [HDR100_1X2]
J20  (no value)  [HDR100_1X2]
J21  (no value)  [HDR100_1X2]
R3  value 3.9k  [0603]
R4  value 3.9k  [0603]
R28  value 3.9k  [0603]
R30  value 3.9k  [0603]
R61  value 37.4k  [0603]
R62  value 37.4k  [0603]
R64  value 11.5k  [0603]
R65  value 11.5k  [0603]
T1  750342271  [760390015]
T2  750342271  [760390015]
TP3  (no value)  [TP-040_RND]
TP4  (no value)  [TP-040_RND]
U12  SN6501DBV  [DBV0005A_N]
U13  SN6501DBV  [DBV0005A_N]
U19  TPS7A3001DGNR  [MSOP8(DGN)]
U20  (no value)  [MSOP8(DGN)]
U21  TLV70450DBV  [DBV0005A_N]
U22  TLV70450DBV  [DBV0005A_N]

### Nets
+5.0V_USH: C96.1 C102.2 D21.1(K) FB12.2 R28.2
+5.0V_VSH: C98.1 C103.2 D22.1(K) FB13.2 R30.2
+5V_CNTL: C71.2 C72.2 C73.2 C74.2 C79.1(+) T1.2 T2.2 U12.2(VCC) U13.2(VCC)
+6V_USH: C114.1 C126.2 C127.1 C138.1 D29.1(K) J18.1 U21.2(IN)
+6V_VSH: C118.1 C129.2 C137.1 C140.1 D32.1(K) J20.1 U22.2(IN)
-5.0V_USH: C89.1 C90.2 D19.2(A) FB9.2 R3.2 TP3.1
-5.0V_VSH: C92.2 C93.1 D20.2(A) FB10.2 R4.2 TP4.1
-6V_USH: C107.2 C115.1 C128.2 C139.2 D30.2(A) J19.1 U19.5(EN) U19.8(VIN)
-6V_VSH: C108.2 C119.1 C130.2 C141.2 D33.2(A) J21.1 U20.5(EN) U20.8(VIN)
DGND: C57.1 C58.1 C71.1 C72.1 C73.1 C74.1 C79.2(-) U12.4(GND) U12.5(GND) U13.4(GND) U13.5(GND)
GND_USH: C57.2 C88.1 C89.2 C90.1 C96.2 C102.1 C107.1 C113.1 C114.2 C115.2 C116.1 C126.1 C127.2 C128.1 C138.2 C139.1 D4.2(A) D14.1(C) D19.1(K) D21.2(A) J1.1 J1.2 J18.2 J19.2 R64.1 T1.4 U19.3(NC) U19.4(GND) U19.9(TPAD) U21.1(GND)
GND_VSH: C58.2 C91.1 C92.1 C93.2 C98.2 C103.1 C108.1 C117.1 C118.2 C119.2 C120.1 C129.1 C130.1 C137.2 C140.2 C141.1 D5.2(A) D15.1(C) D20.1(K) D22.2(A) J3.1 J3.2 J20.2 J21.2 R65.1 T2.4 U20.3(NC) U20.4(GND) U20.9(TPAD) U22.1(GND)
NetC88_2: C88.2 C97.2 FB9.1 R61.2 U19.1(OUT)
NetC91_2: C91.2 C99.2 FB10.1 R62.2 U20.1(OUT)
NetC97_1: C97.1 R61.1 R64.2 U19.2(FB)
NetC99_1: C99.1 R62.1 R65.2 U20.2(FB)
NetC113_2: C113.2 FB12.1 U21.3(OUT)
NetC116_2: C116.2 U19.6(NR/SS)
NetC117_2: C117.2 FB13.1 U22.3(OUT)
NetC120_2: C120.2 U20.6(NR/SS)
NetD4_1: D4.1(C) R3.1
NetD5_1: D5.1(C) R4.1
NetD14_2: D14.2(A) R28.1
NetD15_2: D15.2(A) R30.1
NetD29_2: D29.2(A) D30.1(K) T1.6
NetD32_2: D32.2(A) D33.1(K) T2.6
NetT1_1: T1.1 U12.3(D2)
NetT1_3: T1.3 U12.1(D1)
NetT2_1: T2.1 U13.3(D2)
NetT2_3: T2.3 U13.1(D1)

Not connected (* = marked no-connect by the designer): T1 5; T2 5; U19 7(DNC); U20 7(DNC); U21 4(NC) 5(NC); U22 4(NC) 5(NC)

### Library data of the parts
C57 C58 = 202R18W102KV4E: CAP CER 1000PF 1KV 10% RADIAL; PartNumber: S102K29Y5PN63J5R; Manufacturer: Vishay BC Components; Polarized: N; CompType: Capacitor; Tolerance_%: 0
C71 C73 C89 C93 C96 C98 C114 C115 C118 C119 C127 C128 C130 C137 = C0603C104K5RACTU: as C32 on sheet Pg3-Current Sense
C72 C74 C88 C91 C107 C108 C113 C117 C126 C129 C138-C141 = GMK325AB7106MM-T: as C17 on sheet Pg3-Current Sense
C79 = UUD1E220MCL1GS: as C80 on sheet Pg3-Current Sense
C90 C92 C102 C103 = C2012X5R1H475K125AB: CAP, CERM, 4.7uF, 50V, +/-10%, X5R, 0805; Manufacturer: TDK; Polarized: N; CompType: Capacitor; U/M: EA; Cap_F: 0.0000047; Tolerance_%: 10; Value1: Unknown; VDC_V: 50; TaMin_C: -55; TaMax_C: 85; Cap_Case: 0805
C97 C99 C116 C120 = 06031C103JAT2A: CAP, CERM, 0.01uF, 100V, +/-5%, X7R, 0603; PartNumber: 06031C103J4Z4A; Manufacturer: AVX; Polarized: N; CompType: Capacitor; U/M: EA; Cap_F: 0.00000001; Tolerance_%: 5; ESR_Ohm: 0.098; Value1: 0.098 ohm; VDC_V: 100; TaMin_C: -55; TaMax_C: 125
D4 D5 D14 D15 = LED_LG L29K-G2J1-24-Z: LED SmartLED Green 570NM; Manufacturer: OSRAM; SymbolCreator: x0120606
D19-D22 = DFLZ6V2-7: Diode, Zener, 6.2V, 1W, PowerDI123; Manufacturer: Diodes Inc.; U/M: EA; Power_W: 1; Vz_V: 6.2; RJA_CperW: 110
D29 D30 D32 D33 = MBR0520LT1G: Diode, Schottky, 20V, 0.5A, SOD-123; Manufacturer: Fairchild Semiconductor; U/M: EA; Vf_V: 0.385; Value2: 0.385V; Io_A: 0.5; Vr_V: 20; TJmax_C: 125; RJC_CperW: 150
FB9 FB10 FB12 FB13 = MMZ1608B102C: as FB2 on sheet Pg3-Current Sense
J1 J3 J18-J21 = JUMPER_2X100MIL: as J2 on sheet Pg3-Current Sense
R3 R4 R28 R30 = CRCW06033K90JNEA: RES, 3.9k ohm, 5%, 0.1W, 0603; Manufacturer: Vishay-Dale; CompType: Resistor; Res_ohm: 3900; Value_Code: 3k90; Tolerance_%: 5; Power_W: 0.1; VDC_V: 75; TempCo: 200 ppm/C; EIA_Code: E24; U/M: EA
R61 R62 = RT0603BRD0737KL: RES 37.4K OHM 1/10W .1% 0603 SMD; PartNumber: ERA-3AEB3742V; Manufacturer: Panasonic; CompType: Resistor; Res_ohm: 37000; Value_Code: 37k4; Tolerance_%: 1%; Power_W: 0.1; Value2: 0.1W; VDC_V: 75; TempCo: 25 ppm/C; EIA_Code: E192; U/M: EA
R64 R65 = CRCW060311K5FKEA: RES, 11.5k ohm, 1%, 0.1W, 0603; Manufacturer: Vishay-Dale; CompType: Resistor; Res_ohm: 11500; Value_Code: 11k5; Tolerance_%: 1; Power_W: 0.1; VDC_V: 75; TempCo: 100 ppm/C; EIA_Code: E96; U/M: EA
T1 T2 = TRNSFMR: Transformer 469uH SMD; Manufacturer: Wurth Electronics Midcom
TP3 TP4 = TP-040_RND: as TP6 on sheet Pg3-Current Sense
U12 U13 = SN6501DBV: Transformer Driver for Isolated Power Supplies, DBV0005A; Alternate Manufacturer: None; Manufacturer: Texas Instruments; SymbolCreator: a0411947; CompType: IC; U/M: EA
U19 U20 = TPS7A3001DGNR: -36V, -200mA, Ultralow-Noise, Negative Linear Regulator; Alternate Manufacturer: None; Manufacturer: Texas Instruments; CompType: IC; SymbolCreator: x0120606
U21 U22 = TLV70450DBV: Regulator, LDO, 5V, 0.15A, SOT23-5; Alternate Manufacturer: None; Manufacturer: Texas Instruments; SymbolCreator: x0120606; CompType: IC

## Sheet Pg6-Power supply 2.SchDoc: Isolated Poser Supply 2
size 431 x 279 mm; Date: Not shown in title block; ApprovedBy: Not shown in title block; CheckedBy: Not shown in title block; Author: Not shown in title block; CompanyName: Not shown in title block; Engineer: Not shown in title block; Organization: Not shown in title block; Address1: Not shown in title block; Address2: Not shown in title block; Address3: Not shown in title block; Address4: Not shown in title block; DocumentNumber: 6; Revision: Use project parameter SCH_Rev; SheetNumber: 6; SheetTotal: 7; PageSetup: Record=PageOptions|CenterHorizontal=True|CenterVertical=True|PrintScale=1.00|XCorrection=1.00|YCorrection=1.00|PrintKind=0|BorderSize=5000000|LeftOffset=0|BottomOffset=0|Orientation=2|PaperLength=1000|PaperWidth=1000|Scale=100|PaperSource=15|PrintQuality=600|MediaType=1|DitherType=10|PaperKind=Letter|PrintScaleMode=1
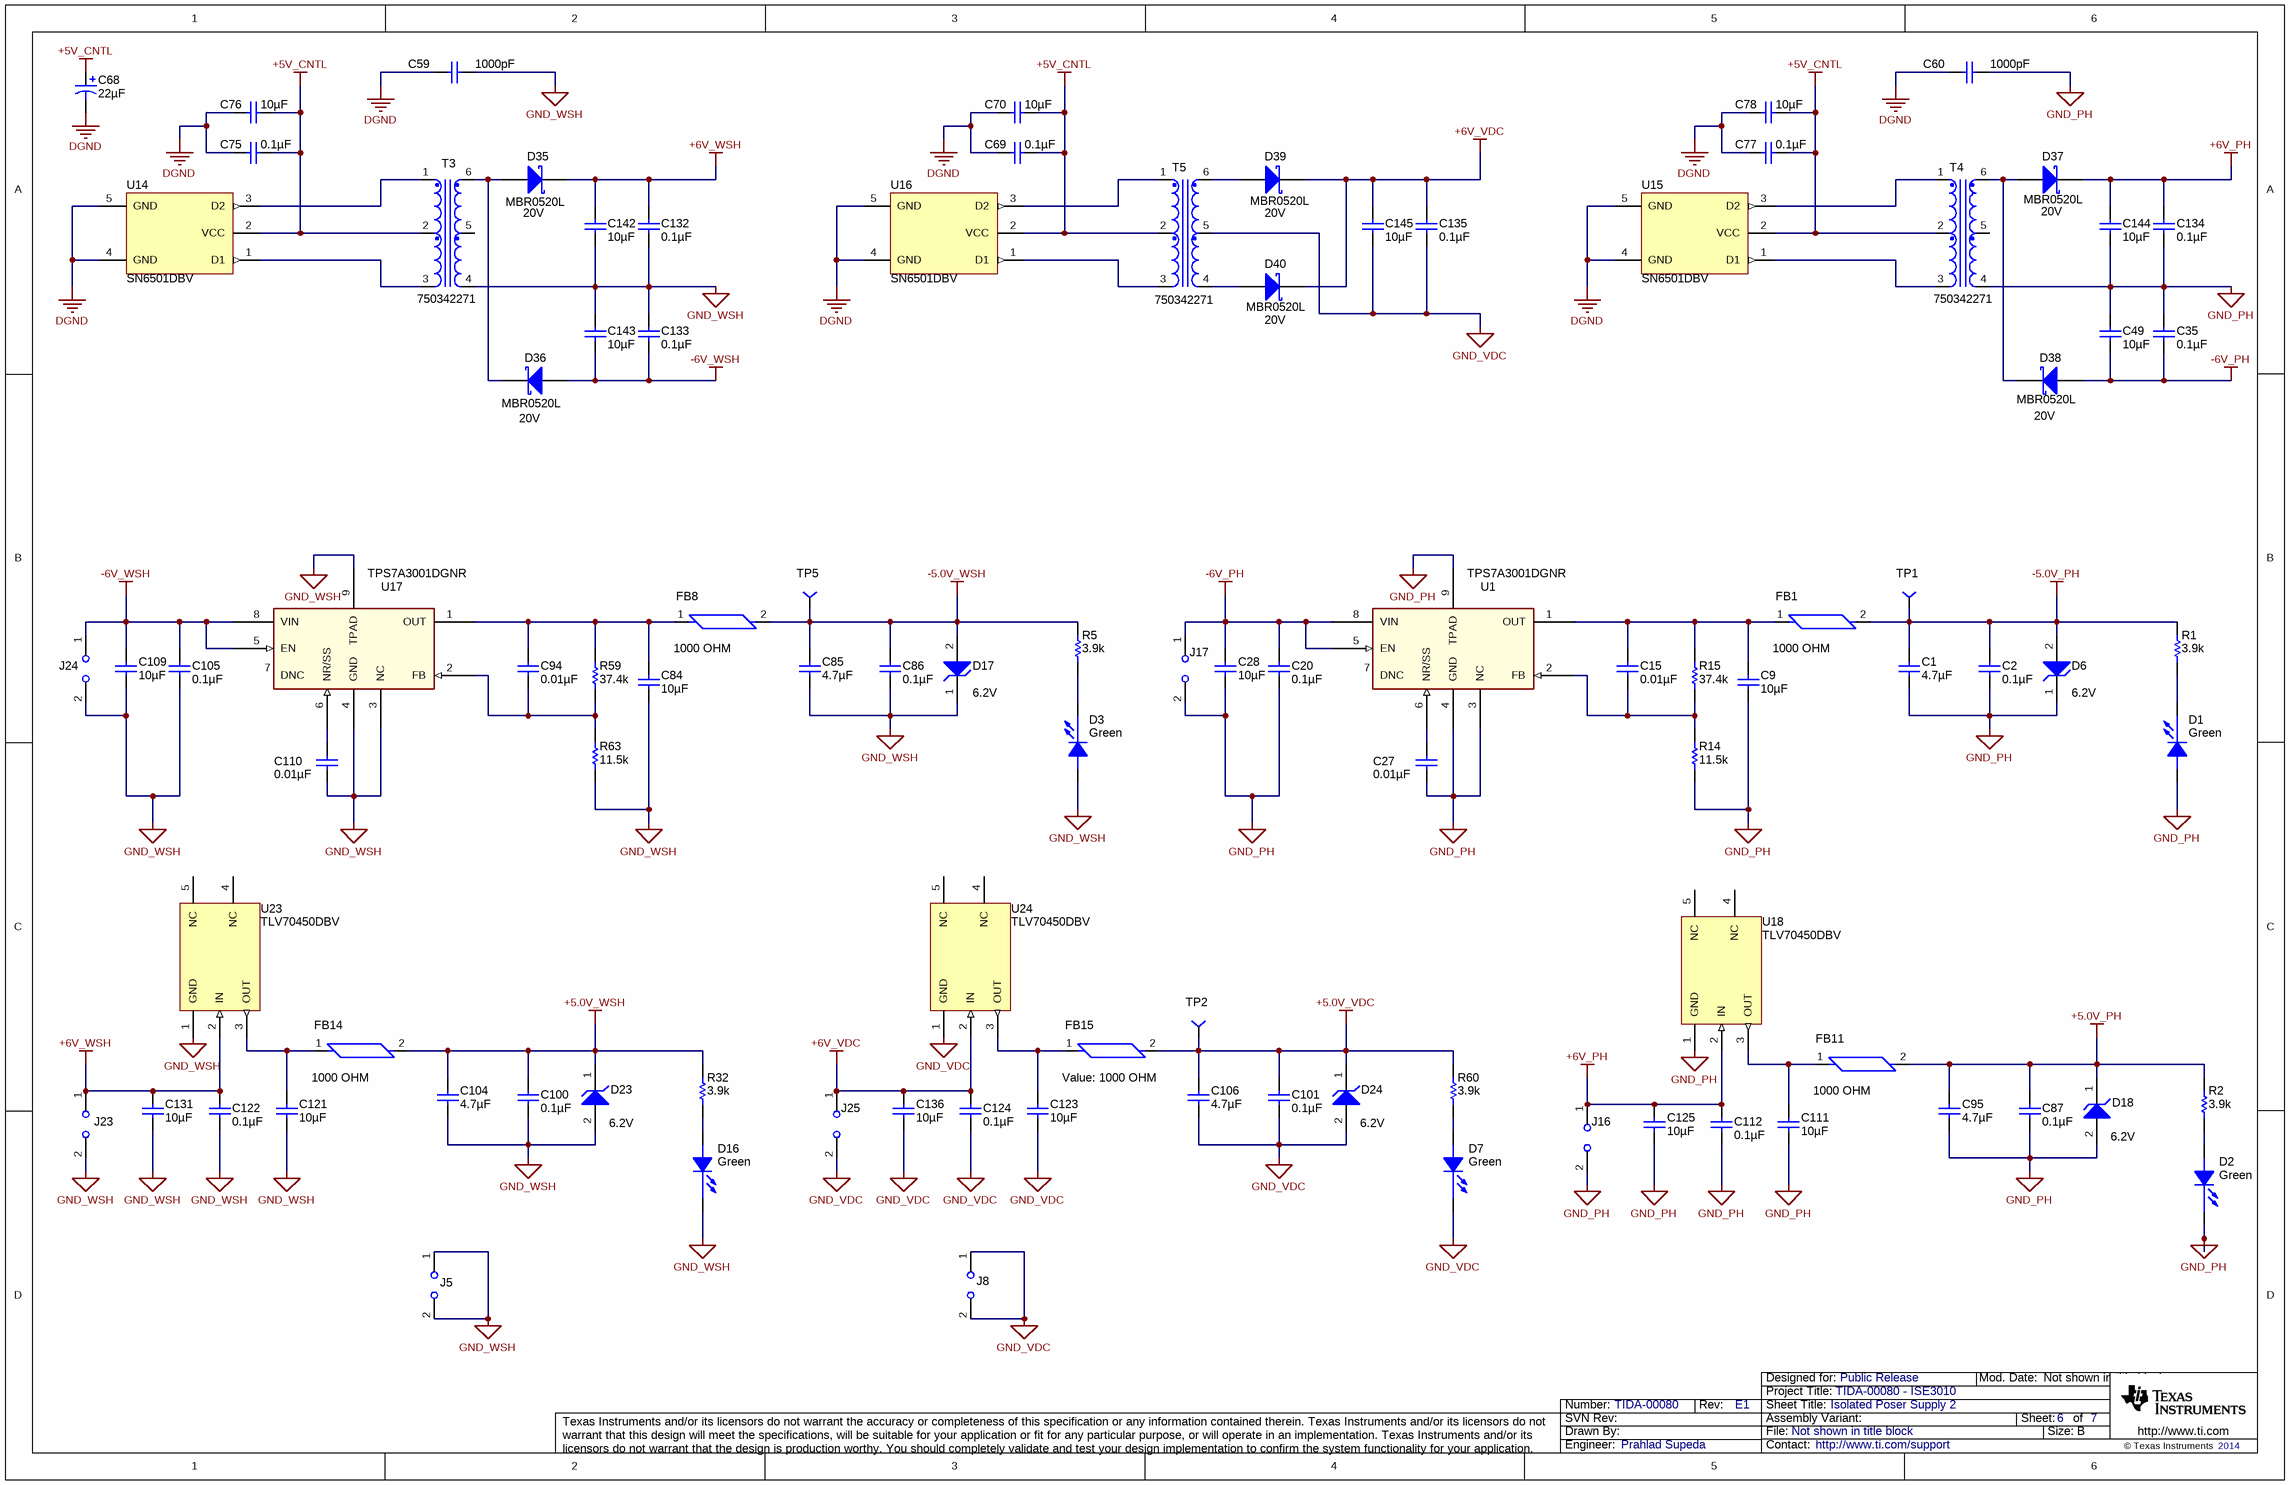
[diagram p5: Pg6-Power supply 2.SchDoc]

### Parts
C1  ValueDisplayed: 4.7µF  [0805_HV]
C2  ValueDisplayed: 0.1µF  [0603]
C9  ValueDisplayed: 10µF  [1210]
C15  ValueDisplayed: 0.01µF  [0603]
C20  ValueDisplayed: 0.1µF  [0603]
C27  ValueDisplayed: 0.01µF  [0603]
C28  ValueDisplayed: 10µF  [1210]
C35  ValueDisplayed: 0.1µF  [0603]
C49  ValueDisplayed: 10µF  [1210]
C59  value 1000pF  [CAP_200mil]
C60  value 1000pF  [CAP_200mil]
C68  ValueDisplayed: 22µF  [SM_RADIAL_5MM]  (hidden comment: UUD1E220MCL1GS)
C69  ValueDisplayed: 0.1µF  [0603]
C70  ValueDisplayed: 10µF  [1210]
C75  ValueDisplayed: 0.1µF  [0603]
C76  ValueDisplayed: 10µF  [1210]
C77  ValueDisplayed: 0.1µF  [0603]
C78  ValueDisplayed: 10µF  [1210]
C84  ValueDisplayed: 10µF  [1210]
C85  ValueDisplayed: 4.7µF  [0805_HV]
C86  ValueDisplayed: 0.1µF  [0603]
C87  ValueDisplayed: 0.1µF  [0603]
C94  ValueDisplayed: 0.01µF  [0603]
C95  ValueDisplayed: 4.7µF  [0805_HV]
C100  ValueDisplayed: 0.1µF  [0603]
C101  ValueDisplayed: 0.1µF  [0603]
C104  ValueDisplayed: 4.7µF  [0805_HV]
C105  ValueDisplayed: 0.1µF  [0603]
C106  ValueDisplayed: 4.7µF  [0805_HV]
C109  ValueDisplayed: 10µF  [1210]
C110  ValueDisplayed: 0.01µF  [0603]
C111  ValueDisplayed: 10µF  [1210]
C112  ValueDisplayed: 0.1µF  [0603]
C121  ValueDisplayed: 10µF  [1210]
C122  ValueDisplayed: 0.1µF  [0603]
C123  ValueDisplayed: 10µF  [1210]
C124  ValueDisplayed: 0.1µF  [0603]
C125  ValueDisplayed: 10µF  [1210]
C131  ValueDisplayed: 10µF  [1210]
C132  ValueDisplayed: 0.1µF  [0603]
C133  ValueDisplayed: 0.1µF  [0603]
C134  ValueDisplayed: 0.1µF  [0603]
C135  ValueDisplayed: 0.1µF  [0603]
C136  ValueDisplayed: 10µF  [1210]
C142  ValueDisplayed: 10µF  [1210]
C143  ValueDisplayed: 10µF  [1210]
C144  ValueDisplayed: 10µF  [1210]
C145  ValueDisplayed: 10µF  [1210]
D1  value Green  [LED0603AA]
D2  value Green  [LED0603AA]
D3  value Green  [LED0603AA]
D6  value 6.2V  [powerDI123]
D7  value Green  [LED0603AA]
D16  value Green  [LED0603AA]
D17  value 6.2V  [powerDI123]
D18  value 6.2V  [powerDI123]
D23  value 6.2V  [powerDI123]
D24  value 6.2V  [powerDI123]
D35  MBR0520L  value 20V  [SOD-123]
D36  MBR0520L  value 20V  [SOD-123]
D37  MBR0520L  value 20V  [SOD-123]
D38  MBR0520L  value 20V  [SOD-123]
D39  MBR0520L  value 20V  [SOD-123]
D40  MBR0520L  value 20V  [SOD-123]
FB1  value 1000 OHM  [FB0603]
FB8  value 1000 OHM  [FB0603]
FB11  value 1000 OHM  [FB0603]
FB14  value 1000 OHM  [FB0603]
FB15  value 1000 OHM  [FB0603]
J5  (no value)  [HDR100_1X2]
J8  (no value)  [HDR100_1X2]
J16  (no value)  [HDR100_1X2]
J17  (no value)  [HDR100_1X2]
J23  (no value)  [HDR100_1X2]
J24  (no value)  [HDR100_1X2]
J25  (no value)  [HDR100_1X2]
R1  value 3.9k  [0603]
R2  value 3.9k  [0603]
R5  value 3.9k  [0603]
R14  value 11.5k  [0603]
R15  value 37.4k  [0603]
R32  value 3.9k  [0603]
R59  value 37.4k  [0603]
R60  value 3.9k  [0603]
R63  value 11.5k  [0603]
T3  750342271  [760390015]
T4  750342271  [760390015]
T5  750342271  [760390015]
TP1  (no value)  [TP-040_RND]
TP2  (no value)  [TP-040_RND]
TP5  (no value)  [TP-040_RND]
U1  (no value)  [MSOP8(DGN)]
U14  SN6501DBV  [DBV0005A_N]
U15  SN6501DBV  [DBV0005A_N]
U16  SN6501DBV  [DBV0005A_N]
U17  (no value)  [MSOP8(DGN)]
U18  TLV70450DBV  [DBV0005A_N]
U23  TLV70450DBV  [DBV0005A_N]
U24  TLV70450DBV  [DBV0005A_N]

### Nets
+5.0V_PH: C87.1 C95.2 D18.1(K) FB11.2 R2.2
+5.0V_VDC: C101.1 C106.2 D24.1(K) FB15.2 R60.2 TP2.1
+5.0V_WSH: C100.1 C104.2 D23.1(K) FB14.2 R32.2
+5V_CNTL: C68.1(+) C69.2 C70.2 C75.2 C76.2 C77.2 C78.2 T3.2 T4.2 T5.2 U14.2(VCC) U15.2(VCC) U16.2(VCC)
+6V_PH: C112.1 C125.2 C134.1 C144.1 D37.1(K) J16.1 U18.2(IN)
+6V_VDC: C124.1 C135.1 C136.2 C145.1 D39.1(K) D40.1(K) J25.1 U24.2(IN)
+6V_WSH: C122.1 C131.2 C132.1 C142.1 D35.1(K) J23.1 U23.2(IN)
-5.0V_PH: C1.2 C2.1 D6.2(A) FB1.2 R1.2 TP1.1
-5.0V_WSH: C85.2 C86.1 D17.2(A) FB8.2 R5.2 TP5.1
-6V_PH: C20.1 C28.2 C35.2 C49.2 D38.2(A) J17.1 U1.5(EN) U1.8(VIN)
-6V_WSH: C105.1 C109.2 C133.2 C143.2 D36.2(A) J24.1 U17.5(EN) U17.8(VIN)
DGND: C59.1 C60.1 C68.2(-) C69.1 C70.1 C75.1 C76.1 C77.1 C78.1 U14.4(GND) U14.5(GND) U15.4(GND) U15.5(GND) U16.4(GND) U16.5(GND)
GND_PH: C1.1 C2.2 C9.1 C20.2 C27.1 C28.1 C35.1 C49.1 C60.2 C87.2 C95.1 C111.1 C112.2 C125.1 C134.2 C144.2 D1.2(A) D2.1(C) D6.1(K) D18.2(A) J16.2 J17.2 R14.1 T4.4 U1.3(NC) U1.4(GND) U1.9(TPAD) U18.1(GND)
GND_VDC: C101.2 C106.1 C123.1 C124.2 C135.2 C136.1 C145.2 D7.1(C) D24.2(A) J8.1 J8.2 J25.2 T5.5 U24.1(GND)
GND_WSH: C59.2 C84.1 C85.1 C86.2 C100.2 C104.1 C105.2 C109.1 C110.1 C121.1 C122.2 C131.1 C132.2 C133.1 C142.2 C143.1 D3.2(A) D16.1(C) D17.1(K) D23.2(A) J5.1 J5.2 J23.2 J24.2 R63.1 T3.4 U17.3(NC) U17.4(GND) U17.9(TPAD) U23.1(GND)
NetC9_2: C9.2 C15.2 FB1.1 R15.2 U1.1(OUT)
NetC15_1: C15.1 R14.2 R15.1 U1.2(FB)
NetC27_2: C27.2 U1.6(NR/SS)
NetC84_2: C84.2 C94.2 FB8.1 R59.2 U17.1(OUT)
NetC94_1: C94.1 R59.1 R63.2 U17.2(FB)
NetC110_2: C110.2 U17.6(NR/SS)
NetC111_2: C111.2 FB11.1 U18.3(OUT)
NetC121_2: C121.2 FB14.1 U23.3(OUT)
NetC123_2: C123.2 FB15.1 U24.3(OUT)
NetD1_1: D1.1(C) R1.1
NetD2_2: D2.2(A) R2.1
NetD3_1: D3.1(C) R5.1
NetD7_2: D7.2(A) R60.1
NetD16_2: D16.2(A) R32.1
NetD35_2: D35.2(A) D36.1(K) T3.6
NetD37_2: D37.2(A) D38.1(K) T4.6
NetD39_2: D39.2(A) T5.6
NetD40_2: D40.2(A) T5.4
NetT3_1: T3.1 U14.3(D2)
NetT3_3: T3.3 U14.1(D1)
NetT4_1: T4.1 U15.3(D2)
NetT4_3: T4.3 U15.1(D1)
NetT5_1: T5.1 U16.3(D2)
NetT5_3: T5.3 U16.1(D1)

Not connected (* = marked no-connect by the designer): T3 5; T4 5; U1 7(DNC); U17 7(DNC); U18 4(NC) 5(NC); U23 4(NC) 5(NC); U24 4(NC) 5(NC)

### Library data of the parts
C1 C85 C95 C104 C106 = C2012X5R1H475K125AB: as C90 on sheet Pg5-Power supply 1
C2 C20 C35 C69 C75 C77 C86 C87 C100 C101 C105 C112 C122 C124 C132-C135 = C0603C104K5RACTU: as C32 on sheet Pg3-Current Sense
C9 C28 C49 C70 C76 C78 C84 C109 C111 C121 C123 C125 C131 C136 C142-C145 = GMK325AB7106MM-T: as C17 on sheet Pg3-Current Sense
C15 C27 C94 C110 = 06031C103JAT2A: CAP, CERM, 0.01uF, 100V, +/-5%, X7R, 0603; Manufacturer: AVX; Polarized: N; CompType: Capacitor; U/M: EA; Cap_F: 0.00000001; Tolerance_%: 5; ESR_Ohm: 0.098; Value1: 0.098 ohm; VDC_V: 100; TaMin_C: -55; TaMax_C: 125
C59 C60 = 202R18W102KV4E: as C57 on sheet Pg5-Power supply 1
C68 = UUD1E220MCL1GS: as C80 on sheet Pg3-Current Sense
D1-D3 D7 D16 = LED_LG L29K-G2J1-24-Z: as D4 on sheet Pg5-Power supply 1
D6 D17 D18 D23 D24 = DFLZ6V2-7: as D19 on sheet Pg5-Power supply 1
D35-D40 = MBR0520LT1G: as D29 on sheet Pg5-Power supply 1
FB1 FB8 FB11 FB14 FB15 = MMZ1608B102C: as FB2 on sheet Pg3-Current Sense
J5 J8 J16 J17 J23-J25 = JUMPER_2X100MIL: as J2 on sheet Pg3-Current Sense
R1 R2 R5 R32 R60 = CRCW06033K90JNEA: as R3 on sheet Pg5-Power supply 1
R14 R63 = CRCW060311K5FKEA: as R64 on sheet Pg5-Power supply 1
R15 R59 = RT0603BRD0737KL: RES 37.4K OHM 1/10W .1% 0603 SMD; PartNumber: ERA-3AEB3742V; Manufacturer: Panasonic; CompType: Resistor; Res_ohm: 37000; Value_Code: 37k4; Tolerance_%: 0.1; Value1: 1%; Value2: 0.1W; VDC_V: 75; TempCo: 25 ppm/C; EIA_Code: E192; U/M: EA
T3-T5 = TRNSFMR: as T1 on sheet Pg5-Power supply 1
TP1 TP2 TP5 = TP-040_RND: as TP6 on sheet Pg3-Current Sense
U1 U17 = TPS7A3001DGNR: as U19 on sheet Pg5-Power supply 1
U14-U16 = SN6501DBV: as U12 on sheet Pg5-Power supply 1
U18 U23 U24 = TLV70450DBV: as U21 on sheet Pg5-Power supply 1

## Sheet Pg7-Hardware.SchDoc: Hardware - MIiscellaneous
size 431 x 279 mm; Date: Not shown in title block; ApprovedBy: Not shown in title block; CheckedBy: Not shown in title block; Author: Not shown in title block; CompanyName: Not shown in title block; Engineer: Not shown in title block; Organization: Not shown in title block; Address1: Not shown in title block; Address2: Not shown in title block; Address3: Not shown in title block; Address4: Not shown in title block; DocumentNumber: 7; Revision: Use project parameter SCH_Rev; SheetNumber: 7; SheetTotal: 7; PageSetup: Record=PageOptions|CenterHorizontal=True|CenterVertical=True|PrintScale=0.62|XCorrection=1.00|YCorrection=1.00|PrintKind=0|BorderSize=5000000|LeftOffset=0|BottomOffset=0|Orientation=2|PaperLength=1000|PaperWidth=1000|Scale=100|PaperSource=15|PrintQuality=600|MediaType=1|DitherType=10|PaperKind=Letter|PrintScaleMode=1
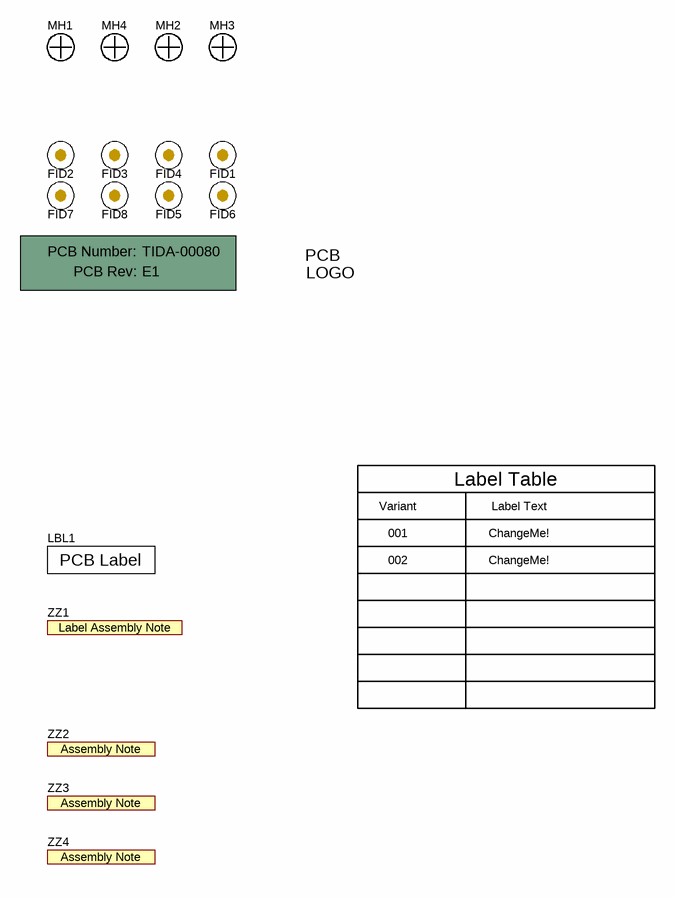
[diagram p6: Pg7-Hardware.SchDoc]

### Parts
!PCB1  (no value)  (mechanical)
FID1  (no value)  [Fiducial10-20]
FID2  (no value)  [Fiducial10-20]
FID3  (no value)  [Fiducial10-20]
FID4  (no value)  [Fiducial10-20]
FID5  (no value)  [Fiducial10-20]
FID6  (no value)  [Fiducial10-20]
FID7  (no value)  [Fiducial10-20]
FID8  (no value)  [Fiducial10-20]
LBL1  (no value)  [Label_650x200]
Logo1  (no value)  [TI_Stacked_SolderMask_Small]  (no BOM)
MH1  (no value)  [MH3.2]
MH2  (no value)  [MH3.2]
MH3  (no value)  [MH3.2]
MH4  (no value)  [MH3.2]
ZZ1  (no value)  [AssemblyNoteLabel]  (no BOM)
ZZ2  (no value)  [AssemblyNote]  (no BOM)
ZZ3  (no value)  [AssemblyNote]  (no BOM)
ZZ4  (no value)  [AssemblyNote]  (no BOM)

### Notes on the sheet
- Variant
- Label Table
- Label Text
- 001
- 002
- ChangeMe!

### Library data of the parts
!PCB1 = PCB: Printed Circuit Board; Manufacturer: Any; PartNumber: TIDA-00080; SymbolCreator: a0412235
FID1-FID8 = Fiducial: Fiducial mark.  There is nothing to buy or mount.; SymbolCreator: codlsc
LBL1 = THT-14-423-10: Thermal Transfer Printable Labels, 0.650" W x 0.200" H - 10,000 per roll; Manufacturer: Brady; SymbolCreator: a0412235; CompType: Label; Note: Size: 0.65" x 0.20 "
Logo1 = TI_Logo: Texas Instrument Corporate Signature; SymbolCreator: codlsc
MH1-MH4 = NY PMS 440 0025 PH: Mountin hole, NPTH Drill 3.2mm; CompType: Hardware
ZZ1 = AssemblyNoteLabel: This Assembly Note is for PCB labels only; SymbolCreator: a0412235
ZZ2 = AssemblyNote: These assemblies are ESD sensitive, ESD precautions shall be observed.; SymbolCreator: codlsc
ZZ3 = AssemblyNote: These assemblies must be clean and free from flux and all contaminants. Use of no clean flux is not acceptable.; SymbolCreator: codlsc
ZZ4 = AssemblyNote: These assemblies must comply with workmanship standards IPC-A-610 Class 2, unless otherwise specified.; SymbolCreator: codlsc

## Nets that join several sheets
+3.3V_DVDD: Pg3-Current Sense (16 pins), Pg4-Voltage signal condtioning (9 pins)
+5.0V_PH: Pg4-Voltage signal condtioning (21 pins), Pg6-Power supply 2 (5 pins)
+5.0V_USH: Pg3-Current Sense (5 pins), Pg5-Power supply 1 (5 pins)
+5.0V_VDC: Pg3-Current Sense (C45.1 J31.2 R37.1), Pg6-Power supply 2 (6 pins)
+5.0V_VSH: Pg3-Current Sense (5 pins), Pg5-Power supply 1 (5 pins)
+5.0V_WSH: Pg3-Current Sense (5 pins), Pg6-Power supply 2 (5 pins)
+5V_CNTL: Pg3-Current Sense (C82.1 C83.1 J32.3 J32.37), Pg5-Power supply 1 (9 pins), Pg6-Power supply 2 (13 pins)
-5.0V_PH: Pg4-Voltage signal condtioning (12 pins), Pg6-Power supply 2 (6 pins)
-5.0V_USH: Pg3-Current Sense (D25.1 D28.1), Pg5-Power supply 1 (6 pins)
-5.0V_VSH: Pg3-Current Sense (D26.1 D31.1), Pg5-Power supply 1 (6 pins)
-5.0V_WSH: Pg3-Current Sense (D27.1 D34.1), Pg6-Power supply 2 (6 pins)
DGND: Pg3-Current Sense (24 pins), Pg4-Voltage signal condtioning (9 pins), Pg5-Power supply 1 (11 pins), Pg6-Power supply 2 (15 pins)
GND_PH: Pg4-Voltage signal condtioning (36 pins), Pg6-Power supply 2 (28 pins)
CLKN_U_PH: Pg3-Current Sense (J32.22), Pg4-Voltage signal condtioning (R49.2)
CLKN_V_PH: Pg3-Current Sense (J32.26), Pg4-Voltage signal condtioning (R52.2)
CLKN_W_PH: Pg3-Current Sense (J32.30), Pg4-Voltage signal condtioning (R54.2)
CLKP_U_PH: Pg3-Current Sense (J32.21), Pg4-Voltage signal condtioning (U8.13)
CLKP_V_PH: Pg3-Current Sense (J32.25), Pg4-Voltage signal condtioning (U9.13)
CLKP_W_PH: Pg3-Current Sense (J32.29), Pg4-Voltage signal condtioning (U10.13)
DOUTN_U_PH: Pg3-Current Sense (J32.20), Pg4-Voltage signal condtioning (R47.2)
DOUTN_V_PH: Pg3-Current Sense (J32.24), Pg4-Voltage signal condtioning (R50.2)
DOUTN_W_PH: Pg3-Current Sense (J32.28), Pg4-Voltage signal condtioning (R53.2)
DOUTP_U_PH: Pg3-Current Sense (J32.19), Pg4-Voltage signal condtioning (R48.2)
DOUTP_V_PH: Pg3-Current Sense (J32.23), Pg4-Voltage signal condtioning (R51.2)
DOUTP_W_PH: Pg3-Current Sense (J32.27), Pg4-Voltage signal condtioning (R55.2)

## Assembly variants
001: not fitted C3 C4 C5 C6 C7 C8 C10 C11 C12 C13 C14 C16 C21 C22 C23 C24 C25 C26 C29 C30 C31 C37 C38 C40 C41 C43 C44 C51 C53 C55 J15 LBL1 R16 R17 R18 U2 U3 U4 U11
